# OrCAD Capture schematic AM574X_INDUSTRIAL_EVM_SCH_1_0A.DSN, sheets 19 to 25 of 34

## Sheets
19 Pg06: Power Supply 2: size C
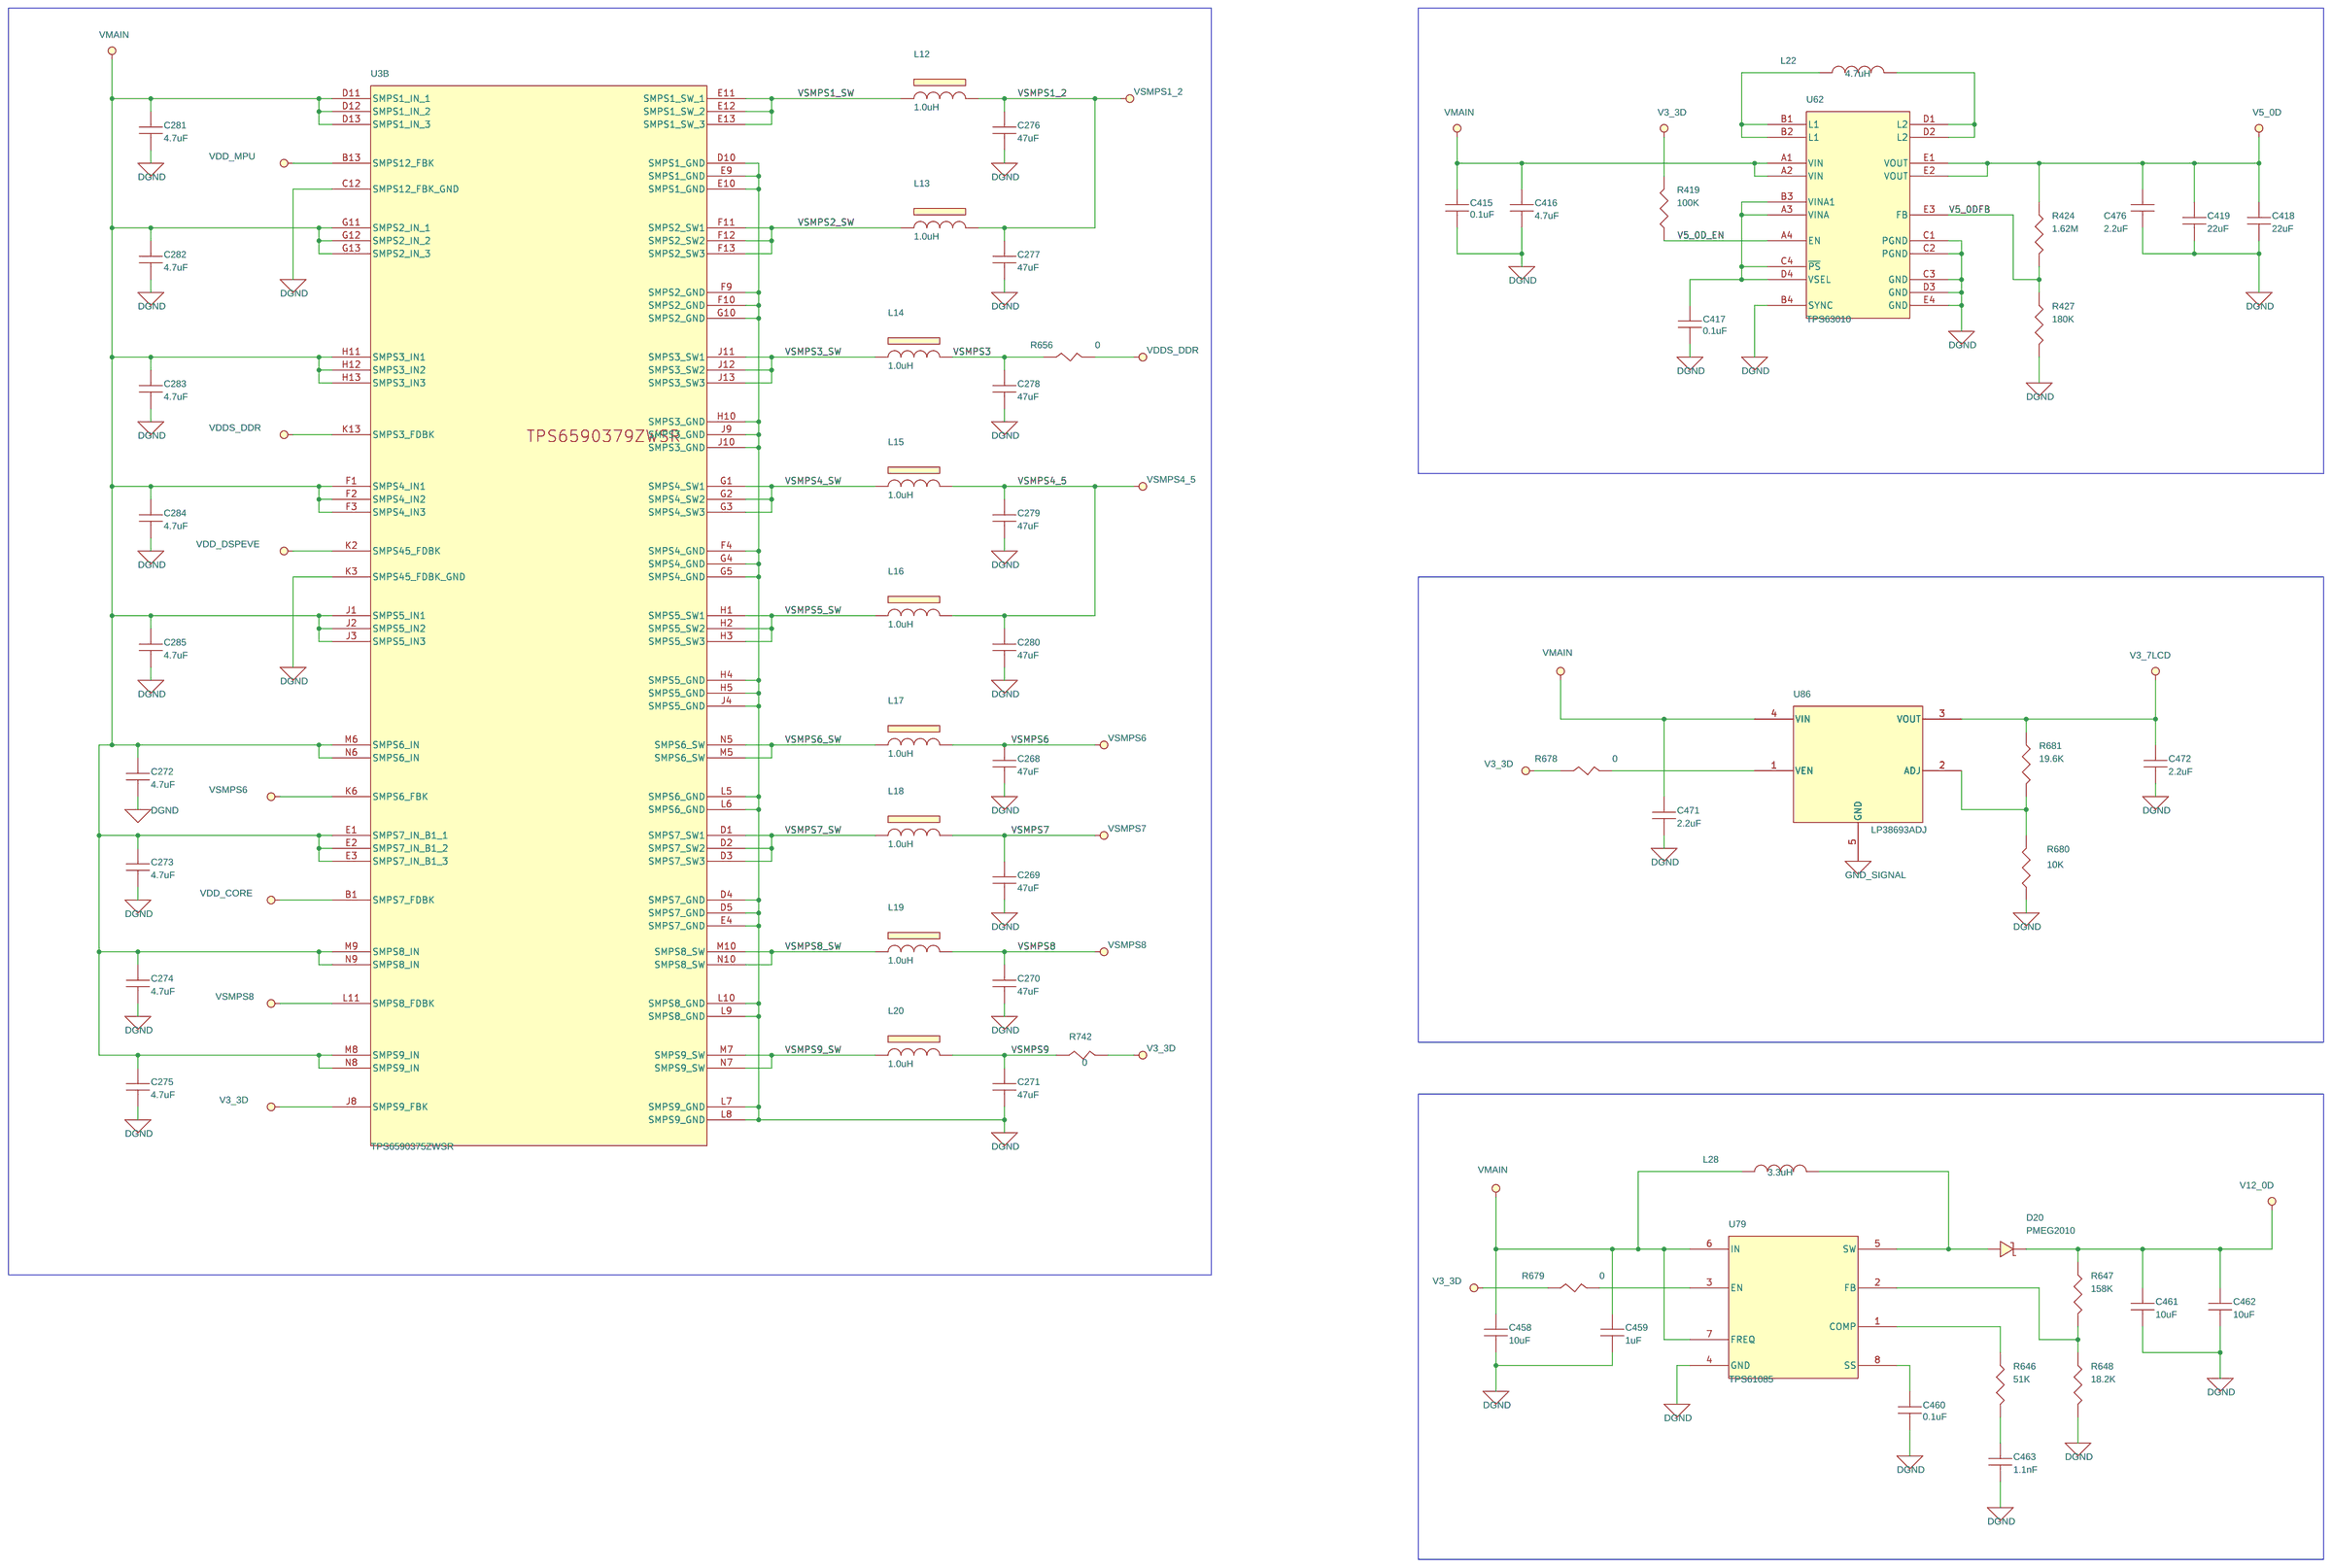
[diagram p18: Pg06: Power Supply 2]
20 Pg05: Power Supply 1: size C
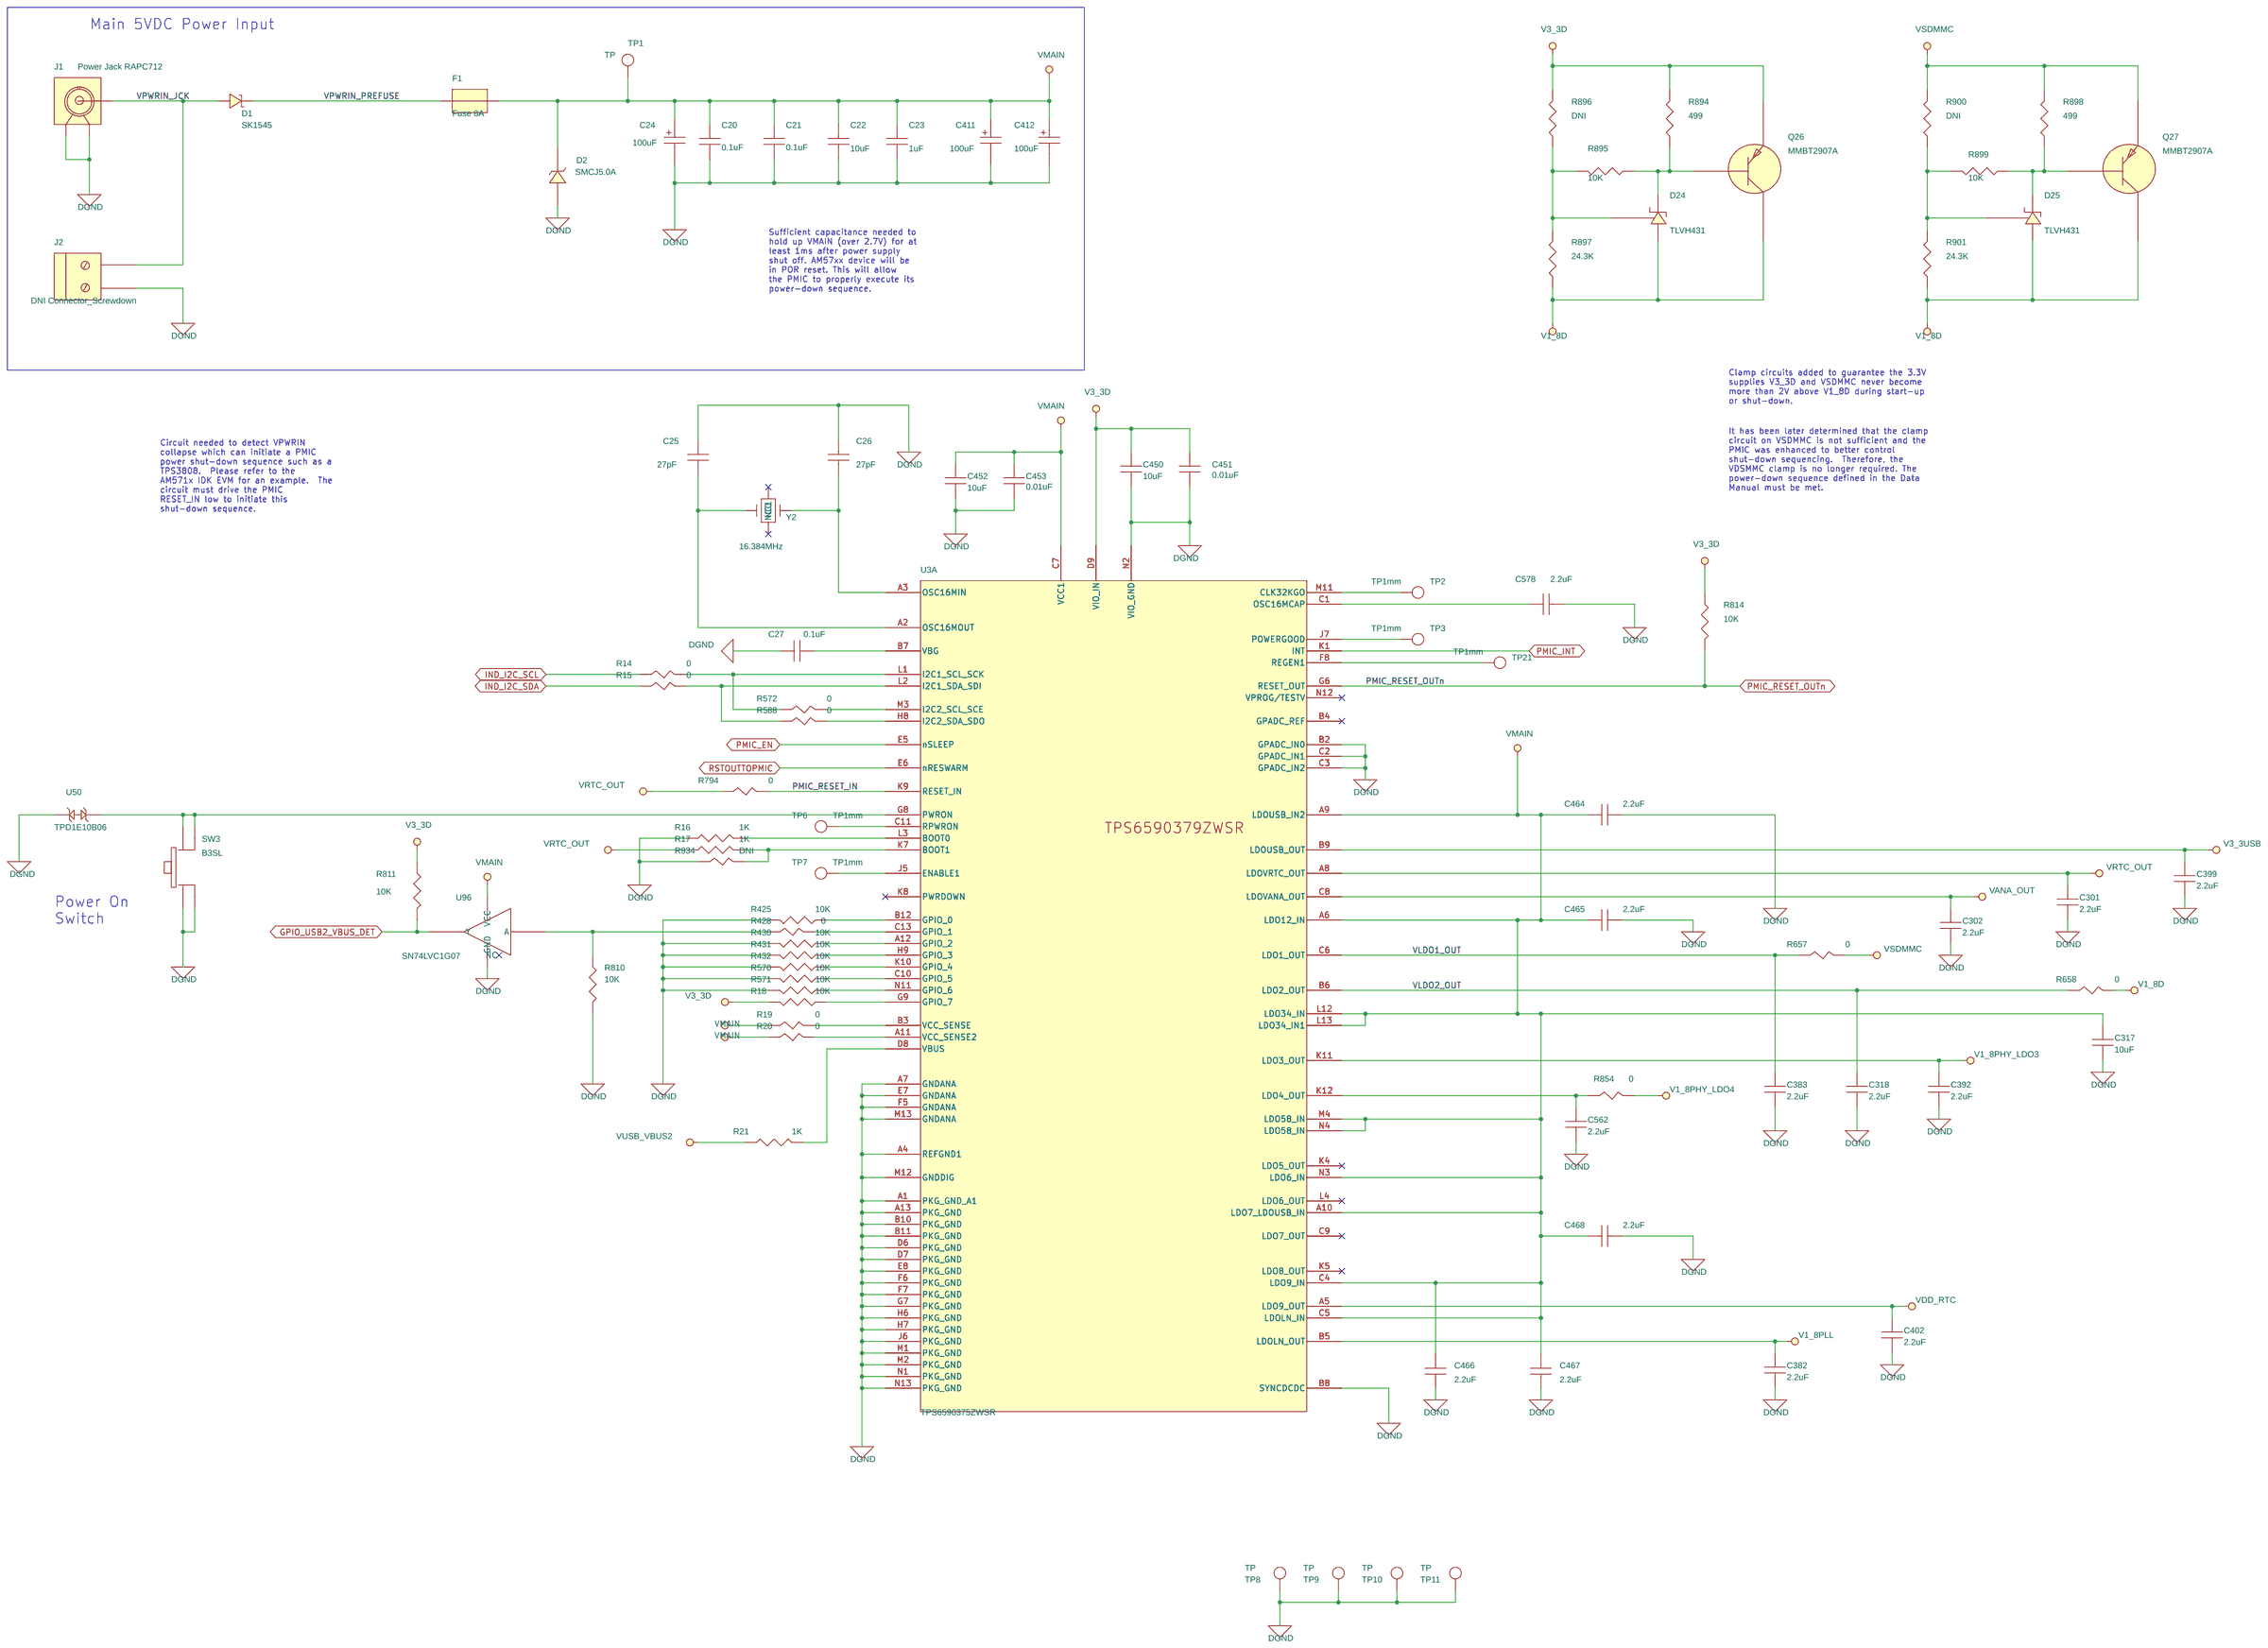
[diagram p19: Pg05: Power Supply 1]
21 Pg20: Industrial I/O: size C
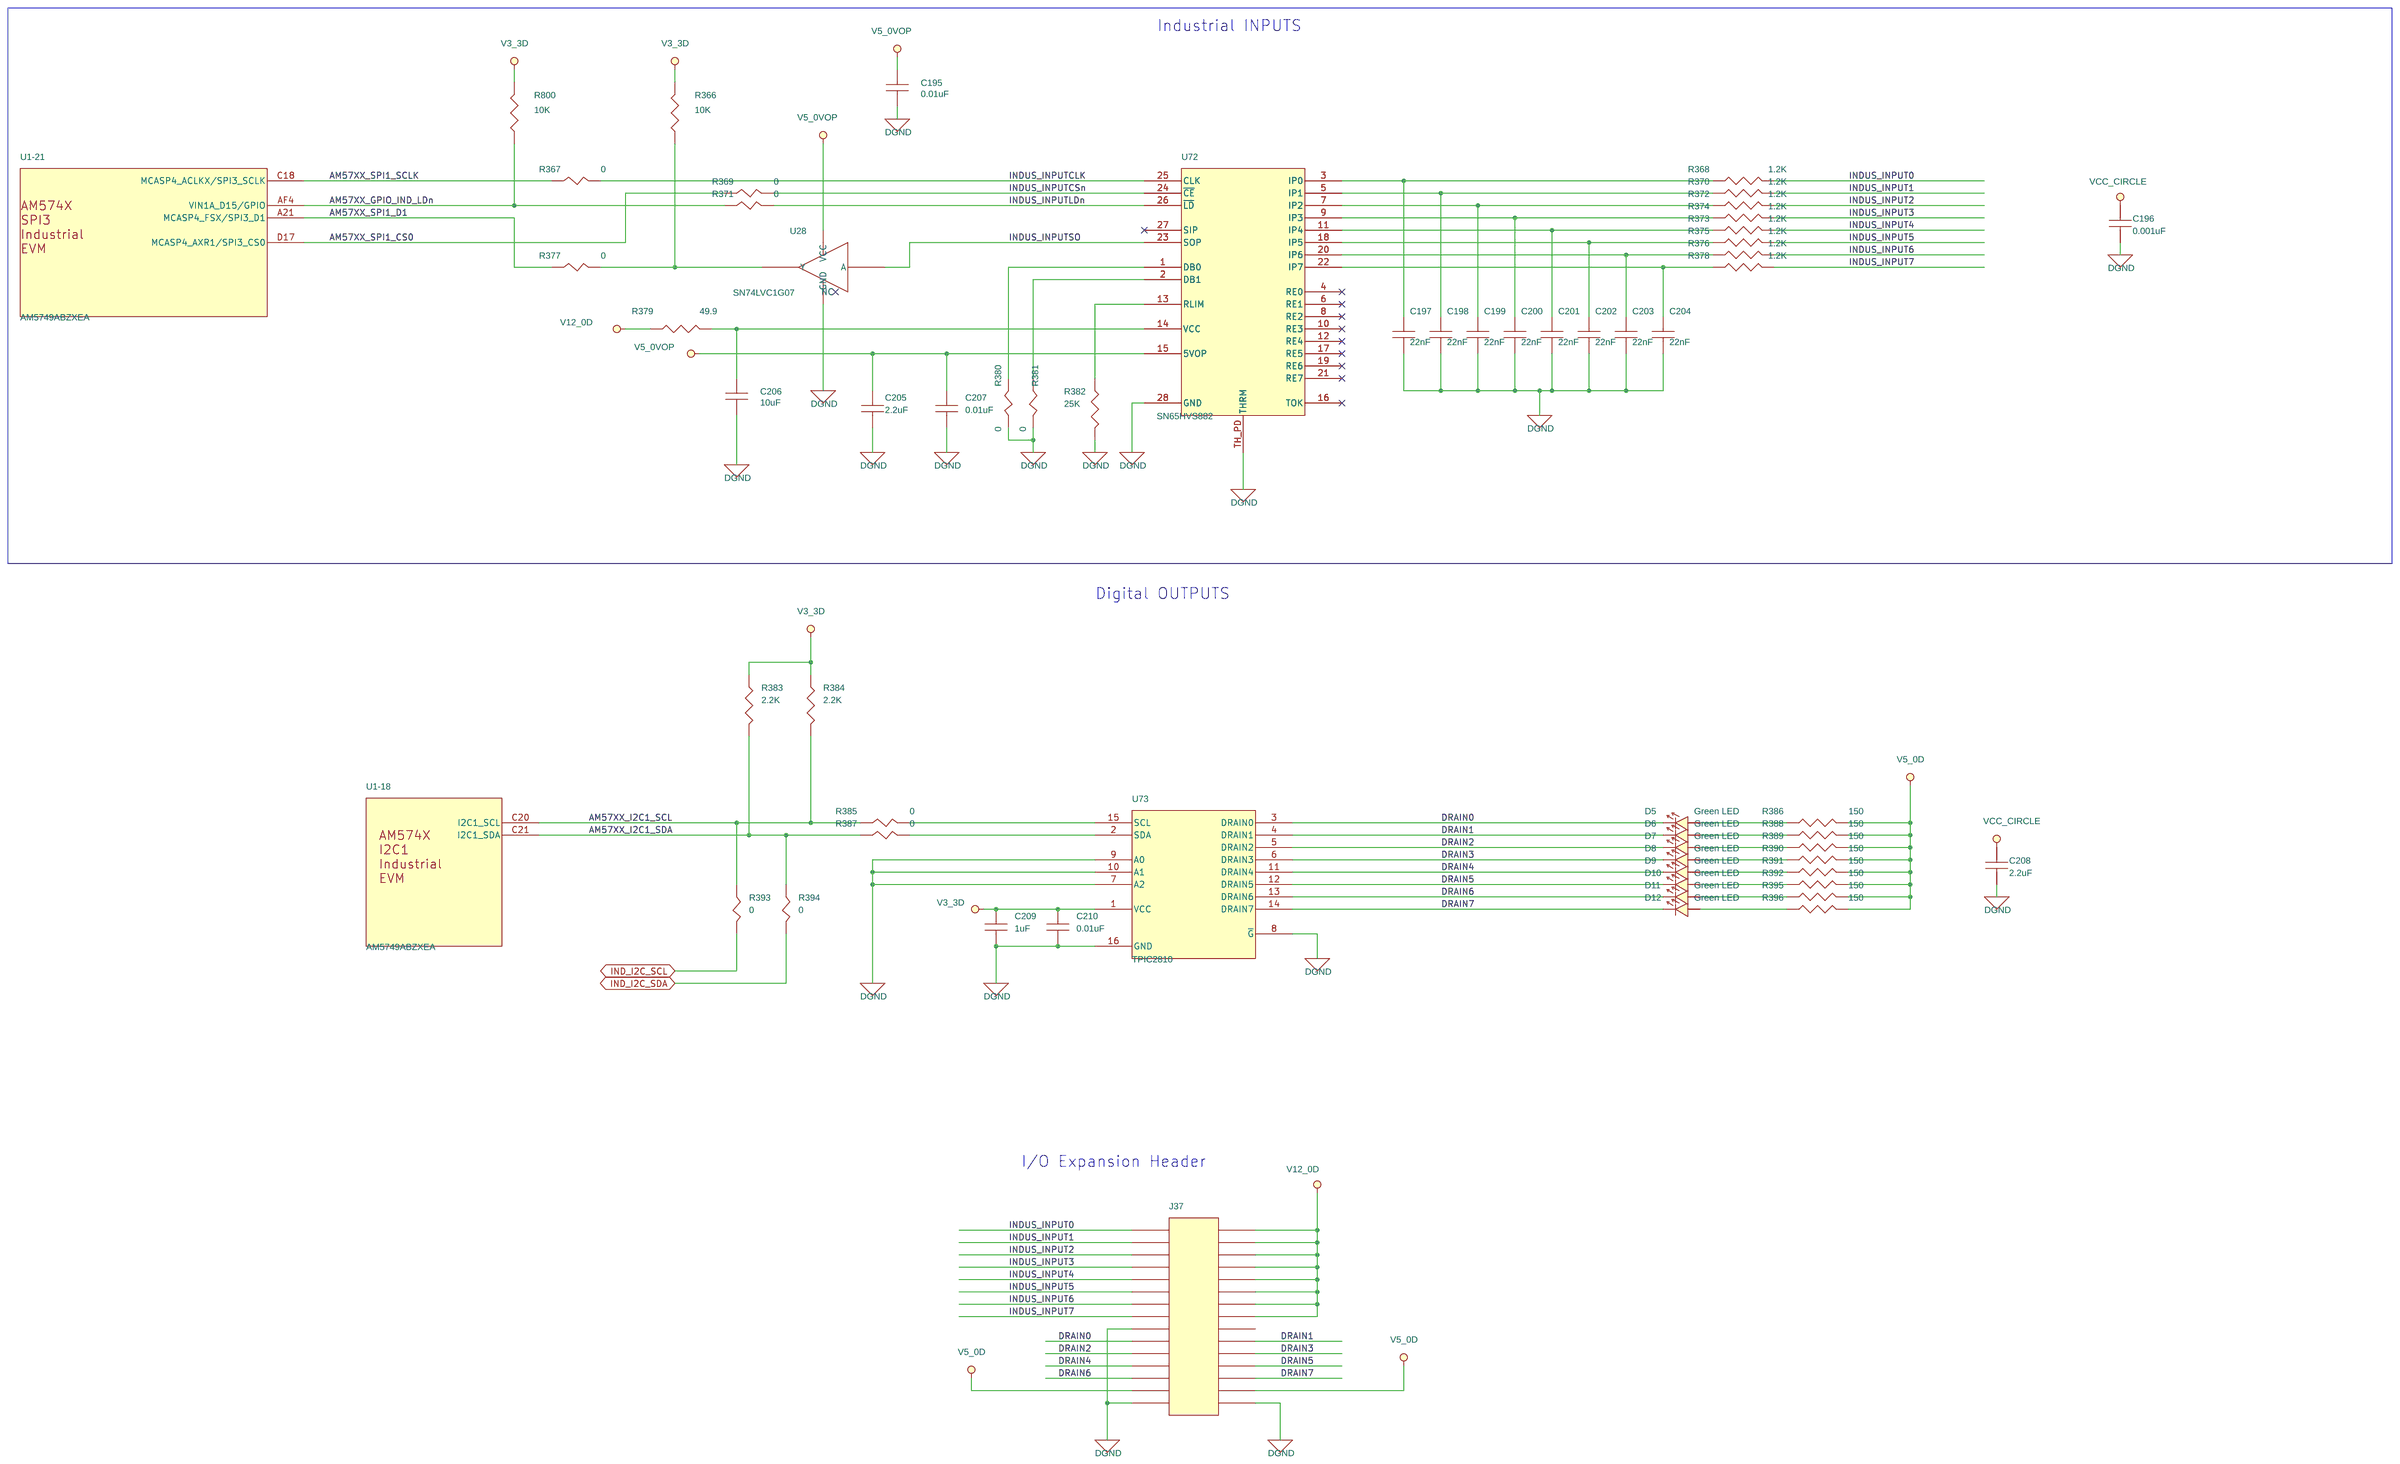
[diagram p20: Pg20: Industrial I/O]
22 Pg11: ICSS1 Ethernet 0: size C
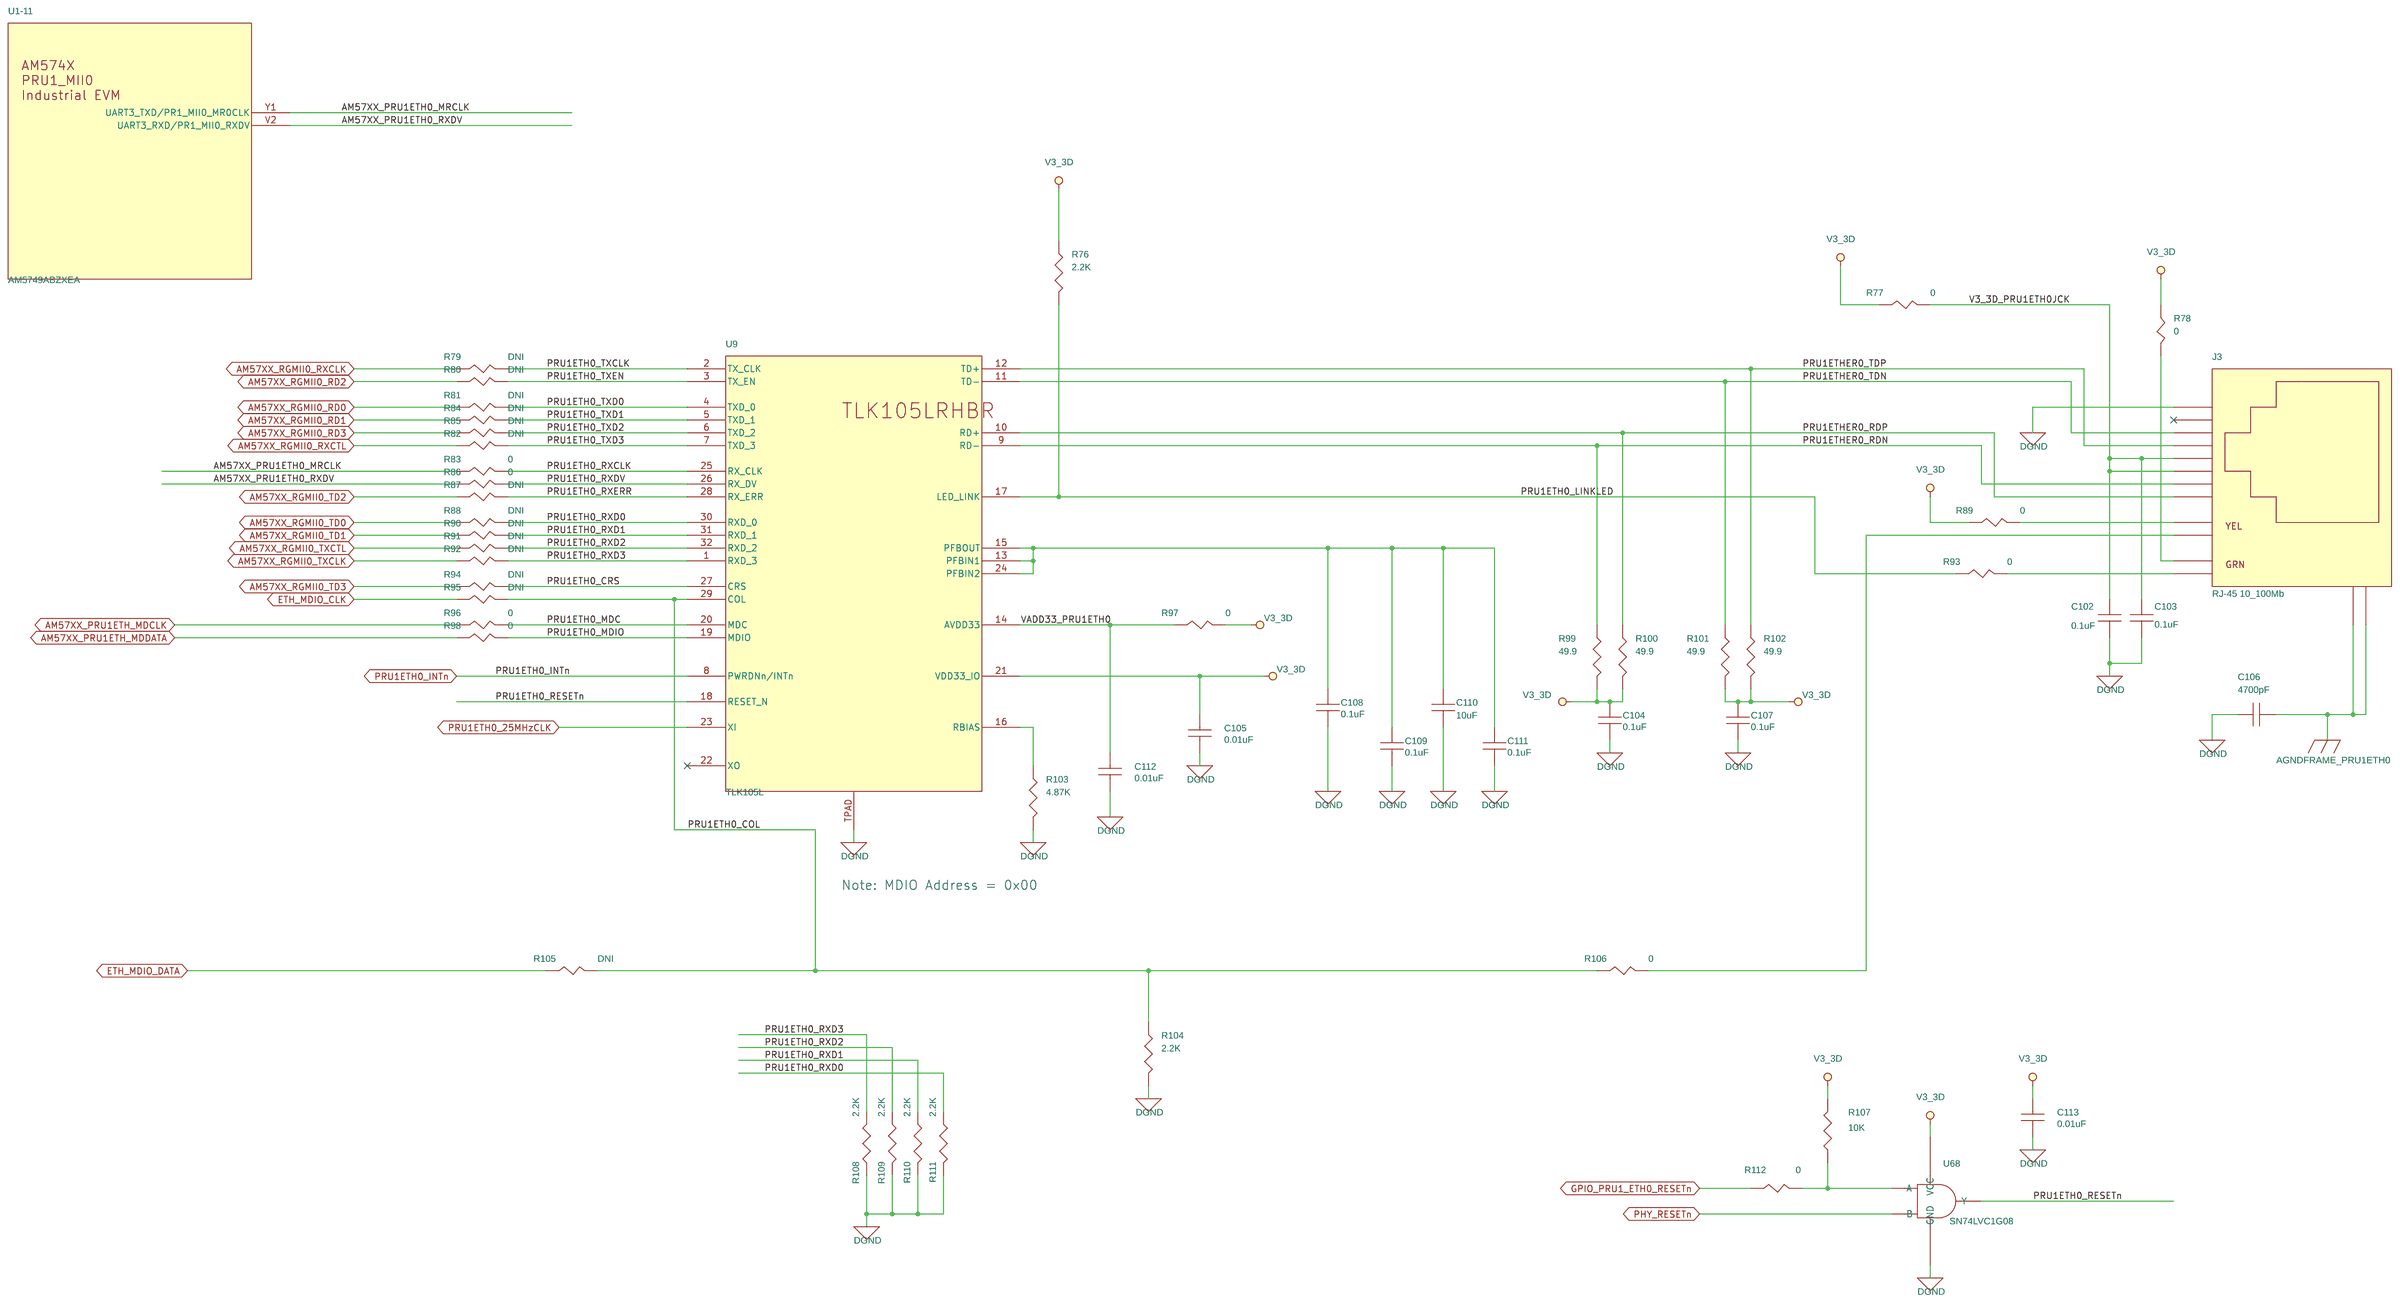
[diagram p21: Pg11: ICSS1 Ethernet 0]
23 Pg03: Processor Power: size C
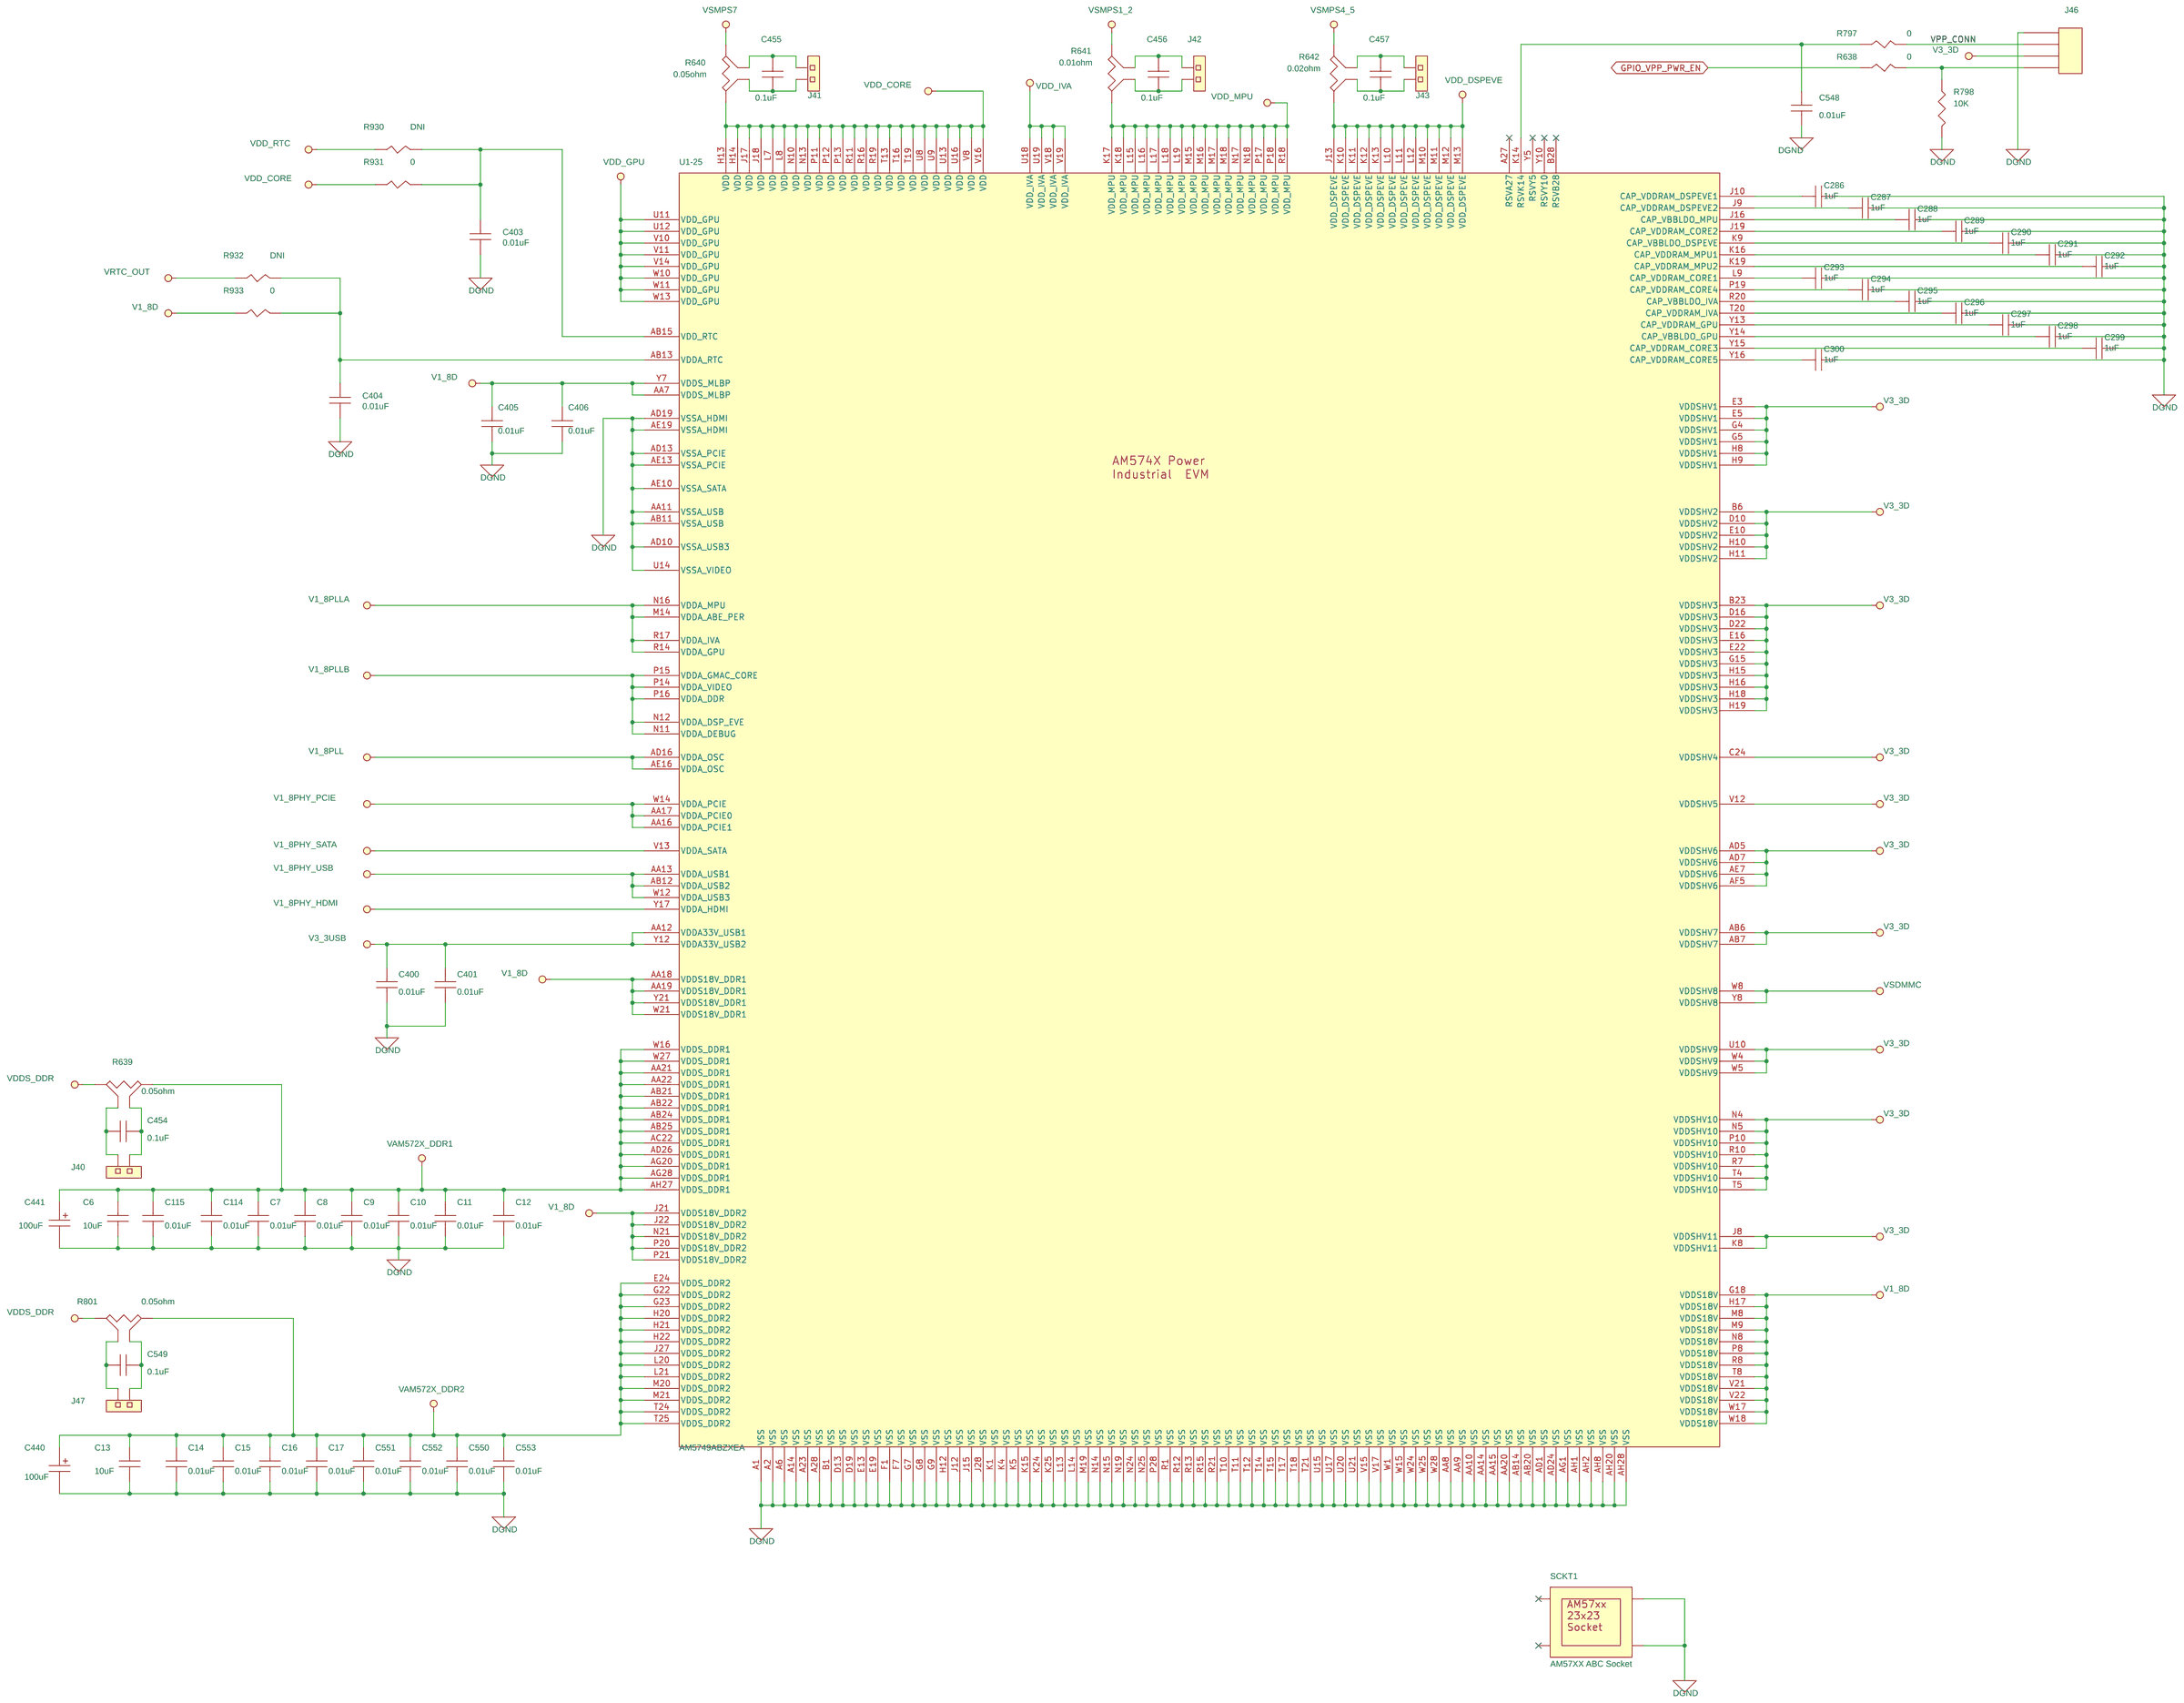
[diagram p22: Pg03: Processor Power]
24 Pg12: ICSS1 Ethernet 1: size C
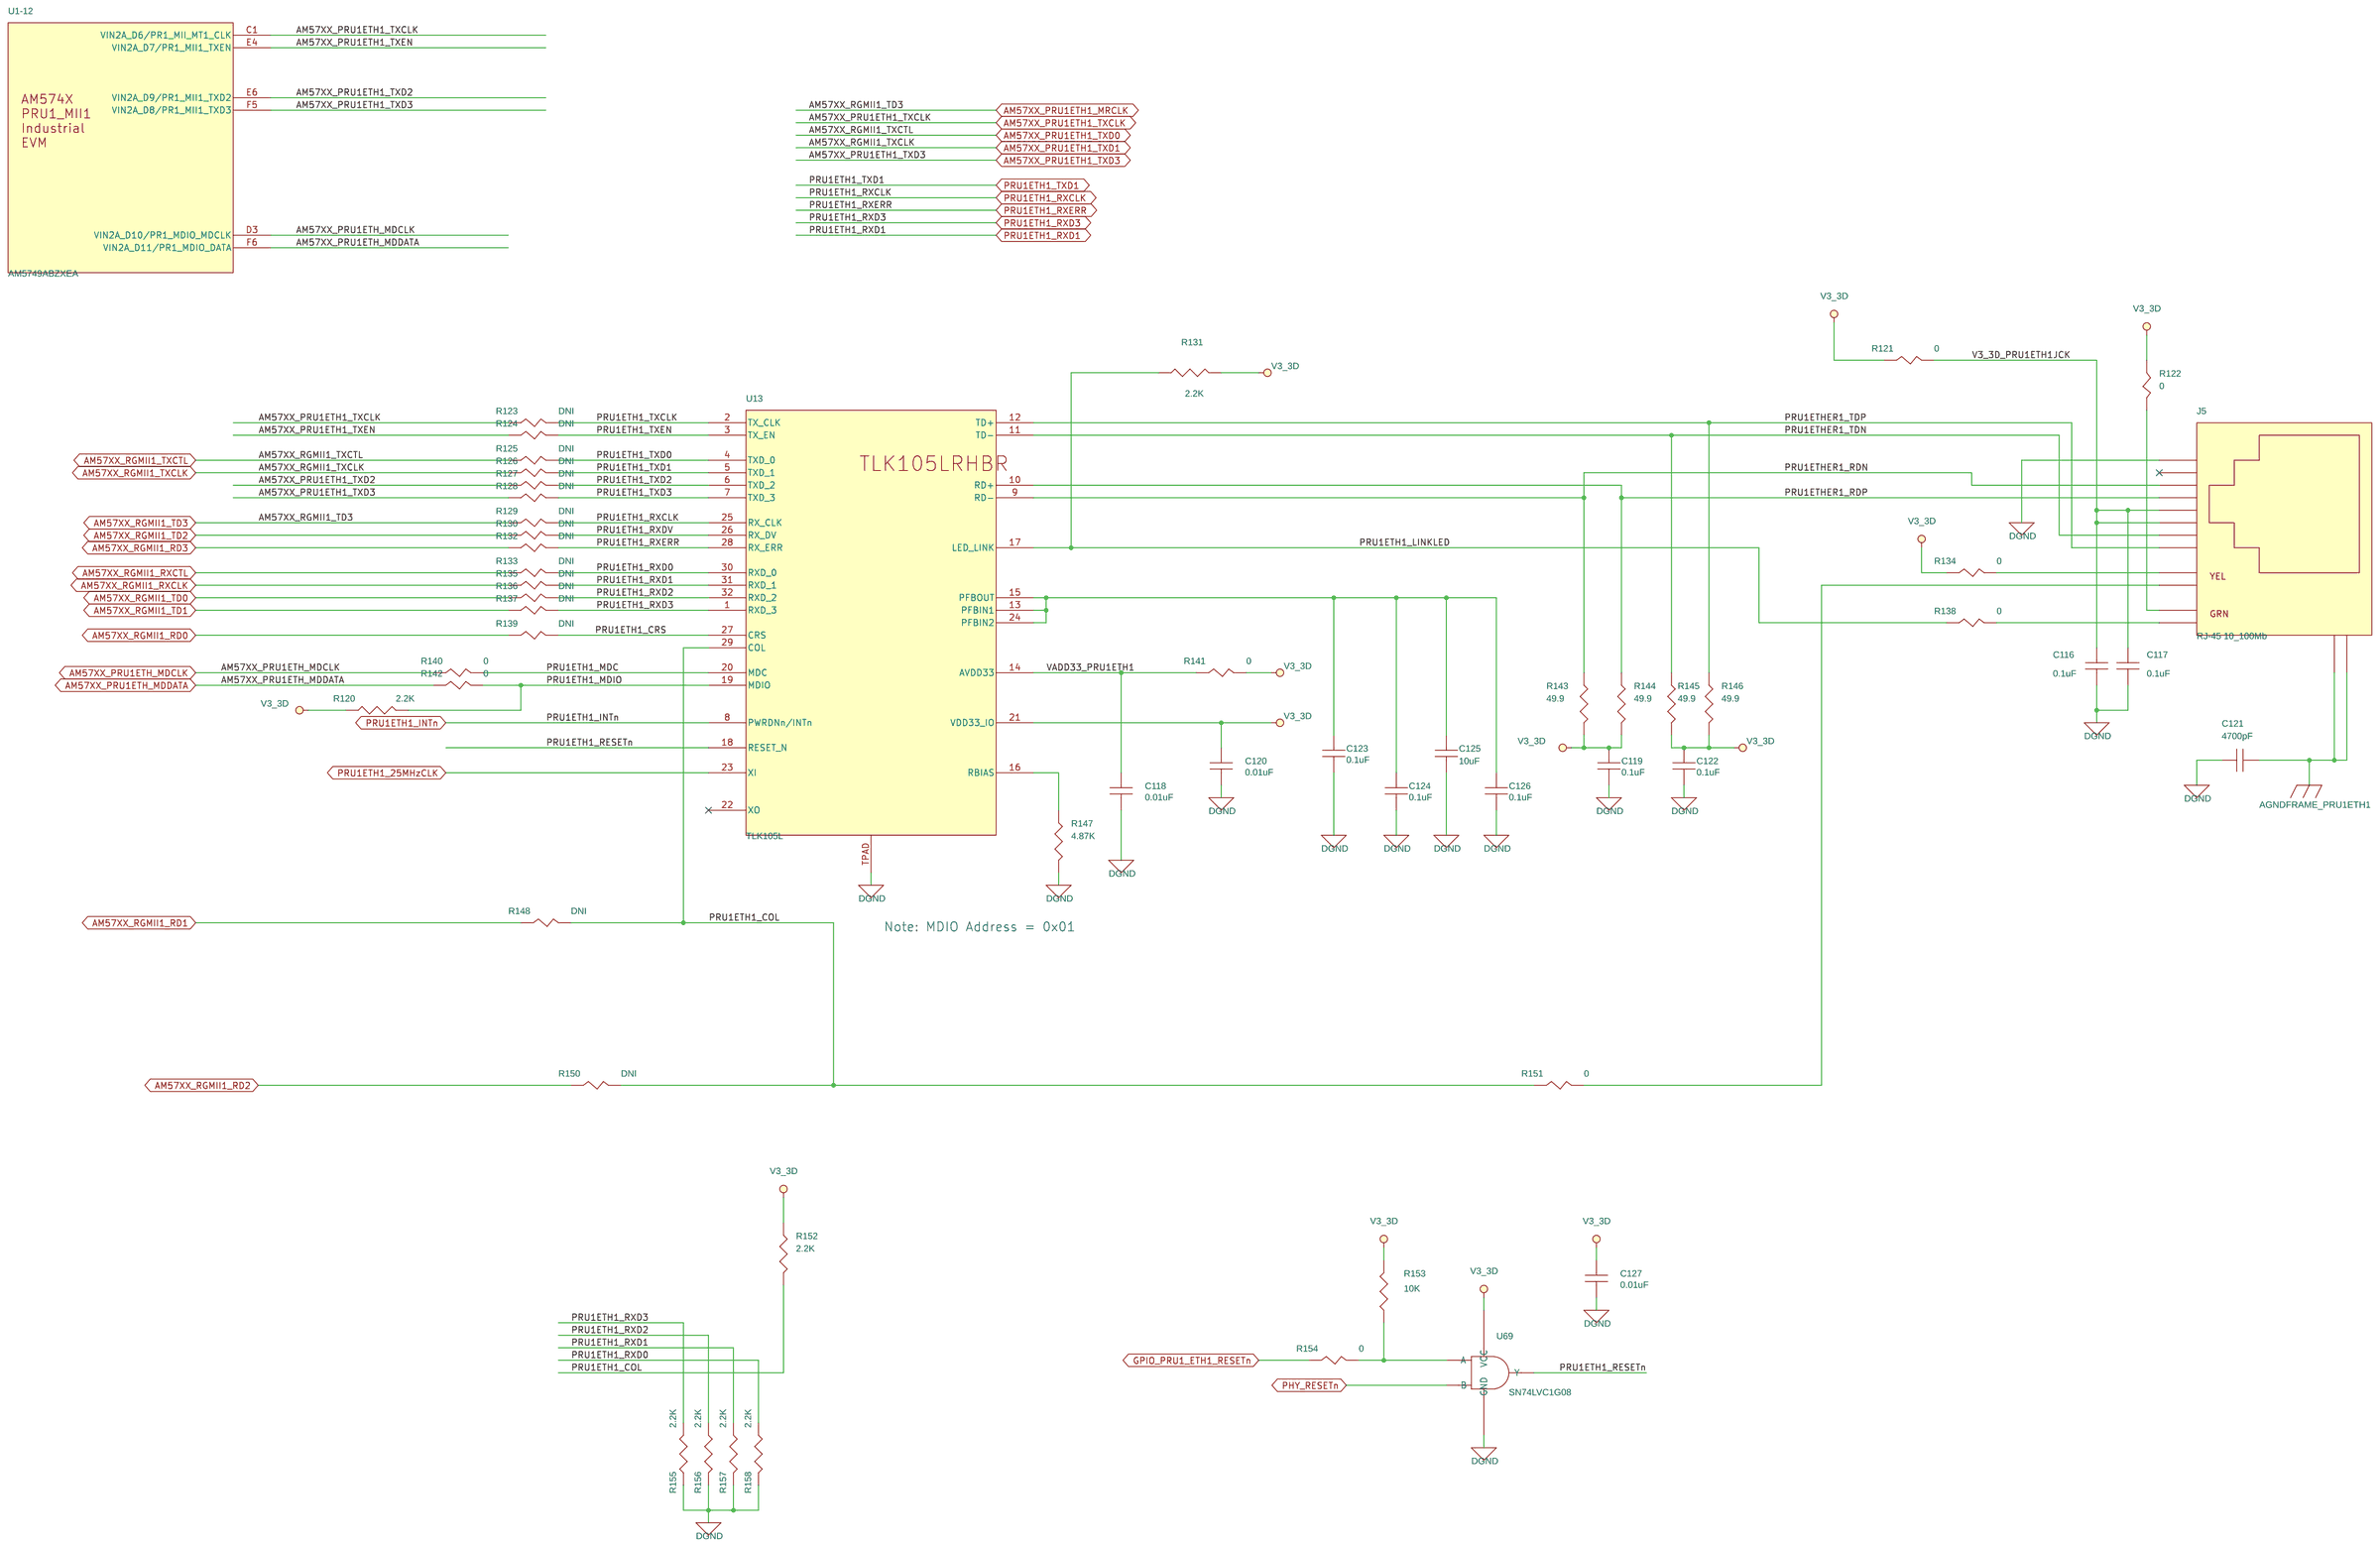
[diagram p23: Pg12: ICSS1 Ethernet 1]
25 Pg07: QSPI Flash Memory: size C
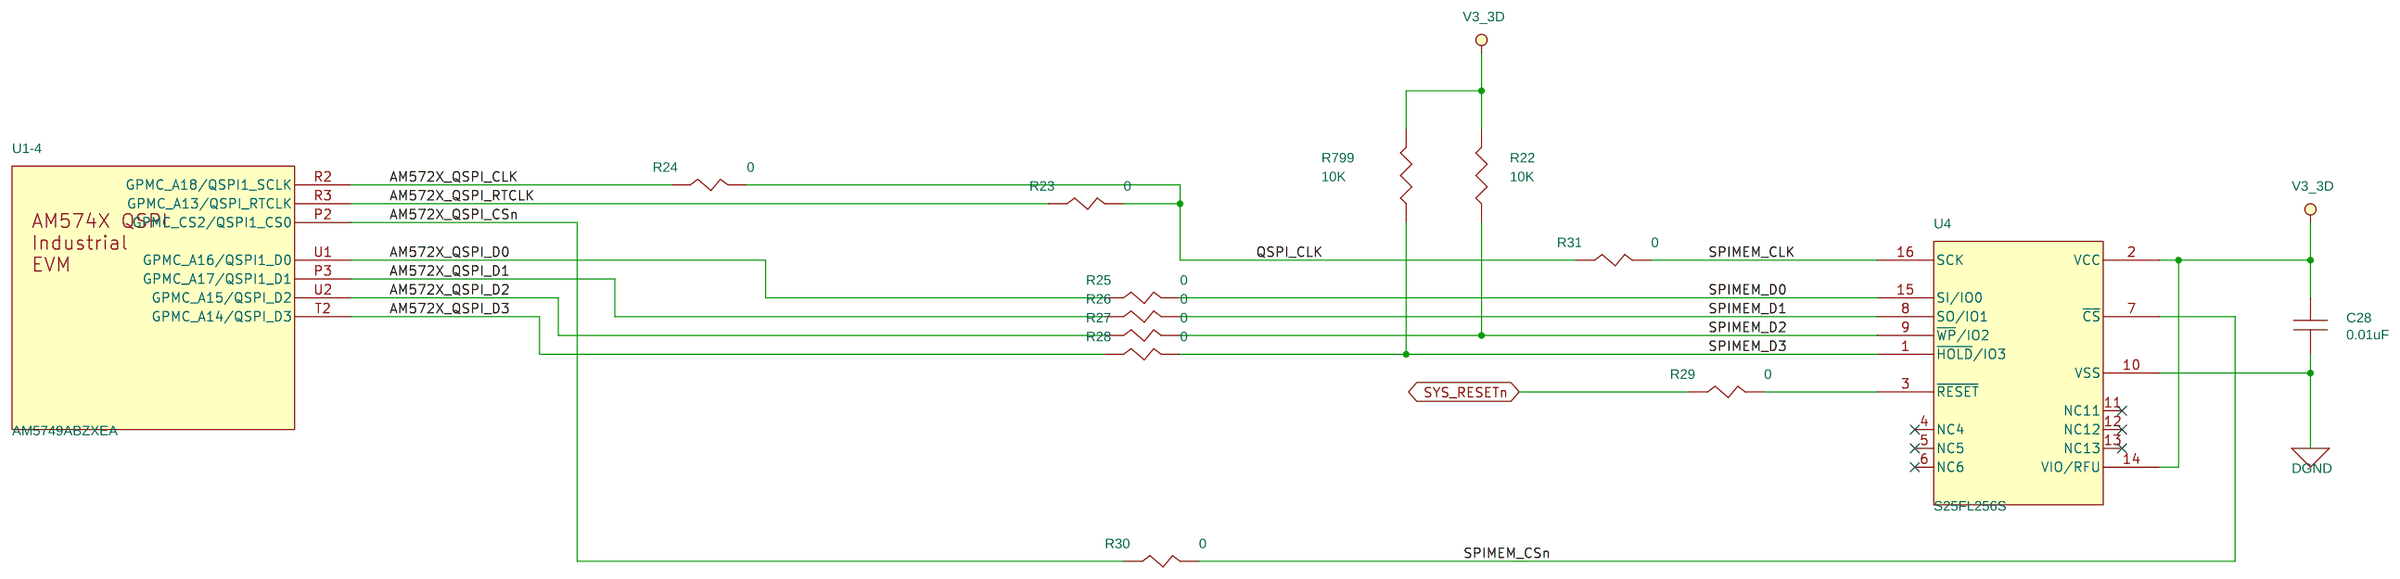
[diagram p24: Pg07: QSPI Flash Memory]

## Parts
sheet Pg03: Processor Power
C6  10uF  [SM-7351-CAP-0805]
C7  0.01uF  [SM-7351-CAP-0402]
C8  0.01uF  [SM-7351-CAP-0402]
C9  0.01uF  [SM-7351-CAP-0402]
C10  0.01uF  [SM-7351-CAP-0402]
C11  0.01uF  [SM-7351-CAP-0402]
C12  0.01uF  [SM-7351-CAP-0402]
C13  10uF  [SM-7351-CAP-0805]
C14  0.01uF  [SM-7351-CAP-0402]
C15  0.01uF  [SM-7351-CAP-0402]
C16  0.01uF  [SM-7351-CAP-0402]
C17  0.01uF  [SM-7351-CAP-0402]
C114  0.01uF  [SM-7351-CAP-0402]
C115  0.01uF  [SM-7351-CAP-0402]
C286  1uF  [SM-7351-CAP-0402]
C287  1uF  [SM-7351-CAP-0402]
C288  1uF  [SM-7351-CAP-0402]
C289  1uF  [SM-7351-CAP-0402]
C290  1uF  [SM-7351-CAP-0402]
C291  1uF  [SM-7351-CAP-0402]
C292  1uF  [SM-7351-CAP-0402]
C293  1uF  [SM-7351-CAP-0402]
C294  1uF  [SM-7351-CAP-0402]
C295  1uF  [SM-7351-CAP-0402]
C296  1uF  [SM-7351-CAP-0402]
C297  1uF  [SM-7351-CAP-0402]
C298  1uF  [SM-7351-CAP-0402]
C299  1uF  [SM-7351-CAP-0402]
C300  1uF  [SM-7351-CAP-0402]
C400  0.01uF  [SM-7351-CAP-0402]
C401  0.01uF  [SM-7351-CAP-0402]
C403  0.01uF  [SM-7351-CAP-0402]
C404  0.01uF  [SM-7351-CAP-0402]
C405  0.01uF  [SM-7351-CAP-0402]
C406  0.01uF  [SM-7351-CAP-0402]
C440  100uF  [SM-7351-CAP-smdcan]
C441  100uF  [SM-7351-CAP-smdcan]
C454  0.1uF  [SM-7351-CAP-0402]
C455  0.1uF  [SM-7351-CAP-0402]
C456  0.1uF  [SM-7351-CAP-0402]
C457  0.1uF  [SM-7351-CAP-0402]
C548  0.01uF  [SM-7351-CAP-0402]
C549  0.1uF  [SM-7351-CAP-0402]
C550  0.01uF  [SM-7351-CAP-0402]
C551  0.01uF  [SM-7351-CAP-0402]
C552  0.01uF  [SM-7351-CAP-0402]
C553  0.01uF  [SM-7351-CAP-0402]
J40  HEADER 2  [header_2x1]
J41  HEADER 2  [header_2x1]
J42  HEADER 2  [header_2x1]
J43  HEADER 2  [header_2x1]
J46  HEADER 4  [HDR1x4-330M]
J47  HEADER 2  [header_2x1]
R638  0  [SM-7351-RES-0402]
R639  0.05ohm  [SM_RES_LVK12]
R640  0.05ohm  [SM_RES_LVK12]
R641  0.01ohm  [SM_RES_LVK12]
R642  0.02ohm  [SM_RES_LVK12]
R797  0  [SM-7351-RES-0402]
R798  10K  [SM-7351-RES-0402]
R801  0.05ohm  [SM_RES_LVK12]
R930  DNI  [SM-7351-RES-0402]
R931  0  [SM-7351-RES-0402]
R932  DNI  [SM-7351-RES-0402]
R933  0  [SM-7351-RES-0402]
SCKT1  AM57XX ABC Socket  [SCK-SG-BGA-6334]
sheet Pg05: Power Supply 1
C20  0.1uF  [SM-7351-CAP-0402]
C21  0.1uF  [SM-7351-CAP-0402]
C22  10uF  [SM-7351-CAP-0805]
C23  1uF  [SM-7351-CAP-0603]
C24  100uF  [SM-7351-CAP-smdcan]
C25  27pF  [SM-7351-CAP-0402]
C26  27pF  [SM-7351-CAP-0402]
C27  0.1uF  [SM-7351-CAP-0402]
C301  2.2uF  [SM-7351-CAP-0402]
C302  2.2uF  [SM-7351-CAP-0402]
C317  10uF  [SM-7351-CAP-0805]
C318  2.2uF  [SM-7351-CAP-0402]
C382  2.2uF  [SM-7351-CAP-0402]
C383  2.2uF  [SM-7351-CAP-0402]
C392  2.2uF  [SM-7351-CAP-0402]
C399  2.2uF  [SM-7351-CAP-0402]
C402  2.2uF  [SM-7351-CAP-0402]
C411  100uF  [SM-7351-CAP-smdcan]
C412  100uF  [SM-7351-CAP-smdcan]
C450  10uF  [SM-7351-CAP-0603]
C451  0.01uF  [SM-7351-CAP-0402]
C452  10uF  [SM-7351-CAP-0603]
C453  0.01uF  [SM-7351-CAP-0402]
C464  2.2uF  [SM-7351-CAP-0805]
C465  2.2uF  [SM-7351-CAP-0805]
C466  2.2uF  [SM-7351-CAP-0805]
C467  2.2uF  [SM-7351-CAP-0805]
C468  2.2uF  [SM-7351-CAP-0805]
C562  2.2uF  [SM-7351-CAP-0402]
C578  2.2uF  [SM-7351-CAP-0805]
D1  SK1545  [sk1545]
D2  SMCJ5.0A  [SMCJ26CA]
D24  TLVH431  [sot23-3-44m]
D25  TLVH431  [sot23-3-44m]
F1  Fuse 8A  [fuse-0154]
J1  Power Jack RAPC712  [RAPC712]
J2  DNI Connector_Screwdown  [conn_osttc02]
Q26  MMBT2907A  [sot23-3-44m]
Q27  MMBT2907A  [sot23-3-44m]
R14  0  [SM-7351-RES-0402]
R15  0  [SM-7351-RES-0402]
R16  1K  [SM-7351-RES-0402]
R17  1K  [SM-7351-RES-0402]
R18  10K  [SM-7351-RES-0402]
R19  0  [SM-7351-RES-0402]
R20  0  [SM-7351-RES-0402]
R21  1K  [SM-7351-RES-0402]
R425  10K  [SM-7351-RES-0402]
R428  0  [SM-7351-RES-0402]
R430  10K  [SM-7351-RES-0402]
R431  10K  [SM-7351-RES-0402]
R432  10K  [SM-7351-RES-0402]
R570  10K  [SM-7351-RES-0402]
R571  10K  [SM-7351-RES-0402]
R572  0  [SM-7351-RES-0402]
R588  0  [SM-7351-RES-0402]
R657  0  [SM-7351-RES-0402]
R658  0  [SM-7351-RES-0402]
R794  0  [SM-7351-RES-0402]
R810  10K  [SM-7351-RES-0402]
R811  10K  [SM-7351-RES-0402]
R814  10K  [SM-7351-RES-0402]
R854  0  [SM-7351-RES-0402]
R894  499  [SM-7351-RES-0402]
R895  10K  [SM-7351-RES-0402]
R896  DNI  [SM-7351-RES-0402]
R897  24.3K  [SM-7351-RES-0402]
R898  499  [SM-7351-RES-0402]
R899  10K  [SM-7351-RES-0402]
R900  DNI  [SM-7351-RES-0402]
R901  24.3K  [SM-7351-RES-0402]
R934  DNI  [SM-7351-RES-0402]
SW3  B3SL  [SW_B3SL-1022P]
TP1  TP  [TH_TP_5002]
TP2  TP1mm  [tp_smd1mmcircle]
TP3  TP1mm  [tp_smd1mmcircle]
TP6  TP1mm  [tp_smd1mmcircle]
TP7  TP1mm  [tp_smd1mmcircle]
TP8  TP  [TH_TP_5002]
TP9  TP  [TH_TP_5002]
TP10  TP  [TH_TP_5002]
TP11  TP  [TH_TP_5002]
TP21  TP1mm  [tp_smd1mmcircle]
U50  TPD1E10B06  [tpd1e10b06-2l]
U96  SN74LVC1G07  [SC70-5-43M]
Y2  16.384MHz  [xtal3225-39m]
sheet Pg06: Power Supply 2
C268  47uF  [SM-7351-CAP-1206]
C269  47uF  [SM-7351-CAP-1206]
C270  47uF  [SM-7351-CAP-1206]
C271  47uF  [SM-7351-CAP-1206]
C272  4.7uF  [SM-7351-CAP-0603]
C273  4.7uF  [SM-7351-CAP-0603]
C274  4.7uF  [SM-7351-CAP-0603]
C275  4.7uF  [SM-7351-CAP-0603]
C276  47uF  [SM-7351-CAP-1206]
C277  47uF  [SM-7351-CAP-1206]
C278  47uF  [SM-7351-CAP-1206]
C279  47uF  [SM-7351-CAP-1206]
C280  47uF  [SM-7351-CAP-1206]
C281  4.7uF  [SM-7351-CAP-0603]
C282  4.7uF  [SM-7351-CAP-0603]
C283  4.7uF  [SM-7351-CAP-0603]
C284  4.7uF  [SM-7351-CAP-0603]
C285  4.7uF  [SM-7351-CAP-0603]
C415  0.1uF  [SM-7351-CAP-0402]
C416  4.7uF  [SM-7351-CAP-0603]
C417  0.1uF  [SM-7351-CAP-0402]
C418  22uF  [SM-7351-CAP-0805]
C419  22uF  [SM-7351-CAP-0805]
C458  10uF  [SM-7351-CAP-0805]
C459  1uF  [SM-7351-CAP-0603]
C460  0.1uF  [SM-7351-CAP-0402]
C461  10uF  [SM-7351-CAP-0805]
C462  10uF  [SM-7351-CAP-0805]
C463  1.1nF  [SM-7351-CAP-0603]
C471  2.2uF  [SM-7351-CAP-0805]
C472  2.2uF  [SM-7351-CAP-0805]
C476  2.2uF  [SM-7351-CAP-0402]
D20  PMEG2010  [DFN1006D-2]
L12  1.0uH  [ind_ihlp1616ab]
L13  1.0uH  [ind_ihlp1616ab]
L14  1.0uH  [ind_ihlp1616ab]
L15  1.0uH  [ind_ihlp1616ab]
L16  1.0uH  [ind_ihlp1616ab]
L17  1.0uH  [ind_ihlp1616ab]
L18  1.0uH  [ind_ihlp1616ab]
L19  1.0uH  [ind_ihlp1616ab]
L20  1.0uH  [ind_ihlp1616ab]
L22  4.7uH  [smd_slf7055t]
L28  3.3uH  [vlcf5020t]
R419  100K  [SM-7351-RES-0402]
R424  1.62M  [SM-7351-RES-0402]
R427  180K  [SM-7351-RES-0402]
R646  51K  [SM-7351-RES-0402]
R647  158K  [SM-7351-RES-0402]
R648  18.2K  [SM-7351-RES-0402]
R656  0  [SM-7351-RES-0603]
R678  0  [SM-7351-RES-0402]
R679  0  [SM-7351-RES-0402]
R680  10K  [SM-7351-RES-0402]
R681  19.6K  [SM-7351-RES-0402]
R742  0  [SM-7351-RES-0603]
U3  TPS6590375ZWSR  [bga12x12-169-55m]  (sections A,B)
U62  TPS63010  [u_20_dsbga]
U79  TPS61085  [MSOP3X3-8-43M]
U86  LP38693ADJ  [SOT-223-5]
sheet Pg07: QSPI Flash Memory
C28  0.01uF  [SM-7351-CAP-0402]
R22  10K  [SM-7351-RES-0402]
R23  0  [SM-7351-RES-0402]
R24  0  [SM-7351-RES-0402]
R25  0  [SM-7351-RES-0402]
R26  0  [SM-7351-RES-0402]
R27  0  [SM-7351-RES-0402]
R28  0  [SM-7351-RES-0402]
R29  0  [SM-7351-RES-0402]
R30  0  [SM-7351-RES-0402]
R31  0  [SM-7351-RES-0402]
R799  10K  [SM-7351-RES-0402]
U4  S25FL256S  [soic_16pin_dw]
sheet Pg11: ICSS1 Ethernet 0
C102  0.1uF  [SM-7351-CAP-0402]
C103  0.1uF  [SM-7351-CAP-0402]
C104  0.1uF  [SM-7351-CAP-0402]
C105  0.01uF  [SM-7351-CAP-0402]
C106  4700pF  [SM-7351-CAP-0402]
C107  0.1uF  [SM-7351-CAP-0402]
C108  0.1uF  [SM-7351-CAP-0402]
C109  0.1uF  [SM-7351-CAP-0402]
C110  10uF  [SM-7351-CAP-0805]
C111  0.1uF  [SM-7351-CAP-0402]
C112  0.01uF  [SM-7351-CAP-0402]
C113  0.01uF  [SM-7351-CAP-0402]
J3  RJ-45 10_100Mb  [CNRJ45-1X1WLED]
R76  2.2K  [sm-7351-res-0402]
R77  0  [SM-7351-RES-0402]
R78  0  [SM-7351-RES-0402]
R79  DNI  [SM-7351-RES-0402]
R80  DNI  [SM-7351-RES-0402]
R81  DNI  [SM-7351-RES-0402]
R82  DNI  [SM-7351-RES-0402]
R83  0  [SM-7351-RES-0402]
R84  DNI  [SM-7351-RES-0402]
R85  DNI  [SM-7351-RES-0402]
R86  0  [SM-7351-RES-0402]
R87  DNI  [SM-7351-RES-0402]
R88  DNI  [SM-7351-RES-0402]
R89  0  [SM-7351-RES-0402]
R90  DNI  [SM-7351-RES-0402]
R91  DNI  [SM-7351-RES-0402]
R92  DNI  [SM-7351-RES-0402]
R93  0  [SM-7351-RES-0402]
R94  DNI  [SM-7351-RES-0402]
R95  DNI  [SM-7351-RES-0402]
R96  0  [SM-7351-RES-0402]
R97  0  [SM-7351-RES-0603]
R98  0  [SM-7351-RES-0402]
R99  49.9  [SM-7351-RES-0402]
R100  49.9  [SM-7351-RES-0402]
R101  49.9  [SM-7351-RES-0402]
R102  49.9  [SM-7351-RES-0402]
R103  4.87K  [SM-7351-RES-0402]
R104  2.2K  [sm-7351-res-0402]
R105  DNI  [SM-7351-RES-0402]
R106  0  [SM-7351-RES-0402]
R107  10K  [SM-7351-RES-0402]
R108  2.2K  [sm-7351-res-0402]
R109  2.2K  [sm-7351-res-0402]
R110  2.2K  [sm-7351-res-0402]
R111  2.2K  [sm-7351-res-0402]
R112  0  [SM-7351-RES-0402]
U9  TLK105L  [qfn5x5-32-39m]
U68  SN74LVC1G08  [sm-so-sc70-5]
sheet Pg12: ICSS1 Ethernet 1
C116  0.1uF  [SM-7351-CAP-0402]
C117  0.1uF  [SM-7351-CAP-0402]
C118  0.01uF  [SM-7351-CAP-0402]
C119  0.1uF  [SM-7351-CAP-0402]
C120  0.01uF  [SM-7351-CAP-0402]
C121  4700pF  [SM-7351-CAP-0402]
C122  0.1uF  [SM-7351-CAP-0402]
C123  0.1uF  [SM-7351-CAP-0402]
C124  0.1uF  [SM-7351-CAP-0402]
C125  10uF  [SM-7351-CAP-0805]
C126  0.1uF  [SM-7351-CAP-0402]
C127  0.01uF  [SM-7351-CAP-0402]
J5  RJ-45 10_100Mb  [CNRJ45-1X1WLED]
R120  2.2K  [sm-7351-res-0402]
R121  0  [SM-7351-RES-0402]
R122  0  [SM-7351-RES-0402]
R123  DNI  [SM-7351-RES-0402]
R124  DNI  [SM-7351-RES-0402]
R125  DNI  [SM-7351-RES-0402]
R126  DNI  [SM-7351-RES-0402]
R127  DNI  [SM-7351-RES-0402]
R128  DNI  [SM-7351-RES-0402]
R129  DNI  [SM-7351-RES-0402]
R130  DNI  [SM-7351-RES-0402]
R131  2.2K  [sm-7351-res-0402]
R132  DNI  [SM-7351-RES-0402]
R133  DNI  [SM-7351-RES-0402]
R134  0  [SM-7351-RES-0402]
R135  DNI  [SM-7351-RES-0402]
R136  DNI  [SM-7351-RES-0402]
R137  DNI  [SM-7351-RES-0402]
R138  0  [SM-7351-RES-0603]
R139  DNI  [SM-7351-RES-0402]
R140  0  [SM-7351-RES-0402]
R141  0  [SM-7351-RES-0603]
R142  0  [SM-7351-RES-0402]
R143  49.9  [SM-7351-RES-0402]
R144  49.9  [SM-7351-RES-0402]
R145  49.9  [SM-7351-RES-0402]
R146  49.9  [SM-7351-RES-0402]
R147  4.87K  [SM-7351-RES-0402]
R148  DNI  [SM-7351-RES-0402]
R150  DNI  [SM-7351-RES-0402]
R151  0  [SM-7351-RES-0402]
R152  2.2K  [sm-7351-res-0402]
R153  10K  [SM-7351-RES-0402]
R154  0  [SM-7351-RES-0402]
R155  2.2K  [sm-7351-res-0402]
R156  2.2K  [sm-7351-res-0402]
R157  2.2K  [sm-7351-res-0402]
R158  2.2K  [sm-7351-res-0402]
U13  TLK105L  [qfn5x5-32-39m]
U69  SN74LVC1G08  [sm-so-sc70-5]
sheet Pg20: Industrial I/O
C195  0.01uF  [SM-7351-CAP-0402]
C196  0.001uF  [SM-7351-CAP-0402]
C197  22nF  [SM-7351-CAP-0402]
C198  22nF  [SM-7351-CAP-0402]
C199  22nF  [SM-7351-CAP-0402]
C200  22nF  [SM-7351-CAP-0402]
C201  22nF  [SM-7351-CAP-0402]
C202  22nF  [SM-7351-CAP-0402]
C203  22nF  [SM-7351-CAP-0402]
C204  22nF  [SM-7351-CAP-0402]
C205  2.2uF  [SM-7351-CAP-0805]
C206  10uF  [SM-7351-CAP-1206]
C207  0.01uF  [SM-7351-CAP-0402]
C208  2.2uF  [SM-7351-CAP-0805]
C209  1uF  [SM-7351-CAP-0402]
C210  0.01uF  [SM-7351-CAP-0402]
D5  Green LED  [sm_led_0805]
D6  Green LED  [sm_led_0805]
D7  Green LED  [sm_led_0805]
D8  Green LED  [sm_led_0805]
D9  Green LED  [sm_led_0805]
D10  Green LED  [sm_led_0805]
D11  Green LED  [sm_led_0805]
D12  Green LED  [sm_led_0805]
J37  Header 15x2 Female  [HDR2X15-344M]
R366  10K  [SM-7351-RES-0402]
R367  0  [SM-7351-RES-0402]
R368  1.2K  [SM-7351-CAP-0805]
R369  0  [SM-7351-RES-0402]
R370  1.2K  [SM-7351-CAP-0805]
R371  0  [SM-7351-RES-0402]
R372  1.2K  [SM-7351-CAP-0805]
R373  1.2K  [SM-7351-CAP-0805]
R374  1.2K  [SM-7351-CAP-0805]
R375  1.2K  [SM-7351-CAP-0805]
R376  1.2K  [SM-7351-CAP-0805]
R377  0  [SM-7351-RES-0402]
R378  1.2K  [SM-7351-CAP-0805]
R379  49.9  [SM-7351-CAP-0805]
R380  0  [SM-7351-RES-0402]
R381  0  [SM-7351-RES-0402]
R382  25K  [SM-7351-RES-0603]
R383  2.2K  [sm-7351-res-0402]
R384  2.2K  [sm-7351-res-0402]
R385  0  [SM-7351-RES-0402]
R386  150  [SM-7351-RES-0402]
R387  0  [SM-7351-RES-0402]
R388  150  [SM-7351-RES-0402]
R389  150  [SM-7351-RES-0402]
R390  150  [SM-7351-RES-0402]
R391  150  [SM-7351-RES-0402]
R392  150  [SM-7351-RES-0402]
R393  0  [SM-7351-RES-0402]
R394  0  [SM-7351-RES-0402]
R395  150  [SM-7351-RES-0402]
R396  150  [SM-7351-RES-0402]
R800  10K  [SM-7351-RES-0402]
U28  SN74LVC1G07  [u_5_dck]
U72  SN65HVS882  [u_28_pwp]
U73  TPIC2810  [u_16_d]
sheet Pg29: Profibus
U1  AM5749ABZXEA  [BGA23X23-760-117M]  (sections -1,-10,-11,-12,-13,-14,-15,-16,-17,-18,-19,-2,-20,-21,-22,-23,-24,-25,-26,-27,-28,-29,-3,-4,-5,-6,-7,-8,-9)

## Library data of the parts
C6 C13 C22 C110 C125 C317 C458 = 1C_10uFCapacitor16V10%0805
C7-C12 C14-C17 C28 C105 C112-C115 C118 C120 C127 C195 C207 C210 C400 C401 C403-C406 C451 C453 C548 C550-C553 = 1C_0.01uFCapacitor16V10%0402
C209 C286-C300 = GRT155R61E105KE01D: DescriptiveText: CAP, CER, 1 UF, 10%, 25V, X5R, 0402; Mfr: MURATA
C24 C411 C412 C440 C441 = 1C_100uFCapacitor16V20%ElecPoly
C20 C21 C102-C104 C107-C109 C111 C116 C117 C119 C122-C124 C126 C415 C417 C454-C457 C460 C549 = C0402C104J4RACTU: DescriptiveText: CAP, CER, 0.1 uF, 16V, 5%, X7R, 0402; Mfr: KEMET
J40-J43 J47 = 2H_Header_0
J46 = 2H_Header_4x1
R14 R15 R19 R20 R23-R31 R77-R96 R98 R105 R106 R112 R121-R130 R132-R137 R139 R140 R142 R148 R150 R151 R154 R367 R369 R371 R377 R380 R381 R385 R387 R393 R394 R428 R572 R588 R638 R657 R658 R678 R679 R794 R797 R854 R930-R934 = 1R_ZeroOhmResistor1_16W0402
R639 R640 R801 = LVK12R050DER
R641 = LVK12R010DER
R642 = LVK12R020FER: DescriptiveText: Resistor 0.02ohm 0.5W Sense 1% 1206
R18 R22 R107 R153 R366 R425 R430-R432 R570 R571 R798-R800 R810 R811 R814 R895 R896 R899 R900 = RMCF0402FT10K0: DescriptiveText: RES, THICK FILM,10K OHM, 1%, 0.063W, SMT0402; Mfr: STACKPOLE ELECTRONICS
SCKT1 = AM57XX_SOCKET: DNI: DNI
C23 C459 = 1C_1uFCapacitor50V10%0603
C25 C26 = C0402C270J5GACTU: DescriptiveText: CAP, CER, 27 PF, 50V, 5%, NP0, 0402; Mfr: KEMET
C27 = C1005X7R1H104K050BE: DescriptiveText: CAP, CER, 0.1UF, 50V, 10%, X7R, 0402; Mfr: TDK CORPORATION
C301 C302 C318 C382 C383 C392 C399 C402 C562 = 1C_2.2uFCapacitor6.3V20%X5R0402
C450 C452 = 1C_10uFCapacitor6.3V20%0603
C205 C208 C464-C468 C471 C472 C578 = 1C_2.2uF16V10%SMD0805
D1 = 1E_Diode_15ARect_rev45V: TIIntPartnumber: _1E0014
D2 = SMCJ5.0A: DescriptiveText: DIODE, TVS DIODE, 5VWM, 9.2VC, SMC; Mfr: LITTEL FUSE
D24 D25 = TLVH431_0: DescriptiveText: Adjustable Precision Shunt Regulator; Mfr: TI; MfrNum: TLVH431CDBZT; PartName: Adjustable Precision Shunt Regulator
F1 = 1P_Fuse_0
J1 = 2J_Conn_PwrJack_RAPC712
J2 = 2C_Conn_LeadScrewDown_2pin
Q26 Q27 = 1Q_MOSFET_PChan_FDT434P_0: DescriptiveText: TRANS GP PNP 60V .6A; Mfr: ON Semi; MfrNum: MMBT2907AWT1G; PartName: TRANS GP PNP 60V .6A
R16 R17 R21 = 1R_1KOhmResistor1_16W0402
R894 R898 = RMCF0402FT499R: DescriptiveText: RES, THICK FILM, 499 OHM, 0.063W, 1%, 0402, SMD; Mfr: STACKPOLE ELECTRONICS
R897 R901 = RMCF0402FT24K3: DescriptiveText: RES, THICK FILM, 24.3K OHM, 1%, 0.063W, SMT0402; Mfr: STACKPOLE ELECTRONICS
SW3 = 2W_Switch_Pushbuttonsmd
TP1 TP8-TP11 = 2H_TestPointThroughHole
TP2 TP3 TP6 TP7 TP21 = 2H_Testpoint_SMD1mmCircle
U50 = TPD1E10B06DPYR
U28 U96 = SN74LVC1G07DCKRE4
Y2 = 1Y_Crystal16.384MHz
C268-C271 C276-C280 = 1C_47uFCapacitor10V20%SMD1206
C272-C275 C281-C285 C416 = 1C_4.7uFCapacitor16V10%0603
C418 C419 = 1C_22uFCapacitor16V10%0805
C461 C462 = 1C_10uFCapacitor35V10%0805
C463 = 1C_1.1nFCapacitor50V5%0603
C476 = 1C_2.2uFCapacitor10V20%smd0402
D20 = PMEG2010BELD,315
L12-L20 = SRP4012TA-1R0M: DescriptiveText: INDUCTOR, POWER, 1.0UH, 4.2A, 20%, SMD; Mfr: BOURNS INC
L22 = 1L_0.1Asmd
L28 = 1L_0.5Asmd
R419 = 1R_100KOhmResistor1_16W0402
R424 = 1R_1.62MOhmResistor1_16W0402
R427 = 1R_180KOhmResistor1_16W0402
R646 = 1R_51Kohm1_16W1%smd0402
R647 = 1R_158Kohm1_16W1%smd0402
R648 = 1R_18.2Kohm1_16W1%smd0402
R97 R138 R141 R656 R742 = 1R_ZeroOhmResistor1_16W0603
R680 = 1R_10KOhmResistor1_10W1%0402
R681 = 1R_19.6KohmResistor1_16W1%0402
U3 = TPS6590379ZWSR
U62 = TPS63010YFFR
U79 = TPS61085DGKT
U86 = LP38693MP-ADJ_NOPB
U4 = 1A_S25FL256S_QSPI
C106 C121 = 1C_4700pFCapacitor50V10%0402
J3 J5 = 2J_ConnectorRJ45_10_100MbAMDIX
R76 R104 R108-R111 R120 R131 R152 R155-R158 R383 R384 = 1R_2.2KOhmResistor1_16W0402
R99-R102 R143-R146 = 1R_49.9OhmResistor1_16W0402
R103 R147 = 1R_4.87Kohm1_16W1%smd0402
U9 U13 = TLK105LRHBR
U68 U69 = SN74LVC1G08DCKR
C196 = 1C_0.001uFCapacitor50V5%0402
C197-C204 = C1005X7R1H223K050BE: DescriptiveText: CAP, CER, 22 nF, 10%, 50V,  X7R, 0402, SMD; Mfr: TDK CORPORATION
C206 = C3216X5R1H106K160AB: DescriptiveText: CAP, CER, 10 UF, 10%, 50V,  X5R, 1206, SMD; Mfr: TDK
D5-D12 = 5988170107F
J37 = 2H_Header15x2_0.1in_Female
R368 R370 R372-R376 R378 = ERJ-6ENF1201V: DescriptiveText: RES, THICK FILM, 1.2K OHM, 1%, 0.125W, SMT0805; Mfr: PANASONIC
R379 = ERJ-6ENF49R9V: DescriptiveText: RES, THICK FILM, 49.9 OHM, 1%, 0.125W, 0805; Mfr: PANASONIC
R382 = 1R_25Kohm1_10W0.1%smd0603
R386 R388-R392 R395 R396 = 1R_150ohm1_16W1%SMD0402
U72 = 1A_SN65HVS882
U73 = 1A_TPIC2810: MfrNum: TPIC2810D
U1 = AM5749ABZXEA: DescriptiveText: Dual Cortex A15 Dual C66X SOC AM574x

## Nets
AGNDFRAME_PRU1ETH0: C106.2 J3.SHLD1 J3.SHLD2
AGNDFRAME_PRU1ETH1: C121.2 J5.SHLD1 J5.SHLD2
DGND: C6.2 C7.2 C8.2 C9.2 C10.2 C11.2 C12.2 C13.2 C14.2 C15.2 C16.2 C17.2 C20.2 C21.2 C22.2 C23.2 C24.2(NEG) C25.1 C26.1 C27.1 C28.2 C102.2 C103.2 C104.2 C105.2 C106.1 C107.2 C108.2 C109.2 C110.2 C111.2 C112.2 C113.2 C114.2 C115.2 C116.2 C117.2 C118.2 C119.2 C120.2 C121.1 C122.2 C123.2 C124.2 C125.2 C126.2 C127.2 C195.2 C196.2 C197.2 C198.2 C199.2 C200.2 C201.2 C202.2 C203.2 C204.2 C205.2 C206.2 C207.2 C208.2 C209.2 C210.2 C268.2 C269.2 C270.2 C271.2 C272.2 C273.2 C274.2 C275.2 C276.2 C277.2 C278.2 C279.2 C280.2 C281.2 C282.2 C283.2 C284.2 C285.2 C286.2 C287.2 C288.2 C289.2 C290.2 C291.2 C292.2 C293.2 C294.2 C295.2 C296.2 C297.2 C298.2 C299.2 C300.2 C301.2 C302.2 C317.2 C318.2 C382.2 C383.2 C392.2 C399.2 C400.2 C401.2 C402.2 C403.2 C404.2 C405.2 C406.2 C411.2(NEG) C412.2(NEG) C415.2 C416.2 C417.2 C418.2 C419.2 C440.2(NEG) C441.2(NEG) C450.2 C451.2 C452.2 C453.2 C458.2 C459.2 C460.2 C461.2 C462.2 C463.2 C464.2 C465.2 C466.1 C467.1 C468.2 C471.2 C472.2 C476.2 C548.2 C550.2 C551.2 C552.2 C553.2 C562.2 C578.2 D2.2 J1.2 J1.3 J2.2 J3.8 J5.8 J37.17 J37.29 J37.30 J46.1 R16.2(P2) R103.1(P1) R104.1(P1) R108.1(P1) R109.1(P1) R110.1(P1) R111.1(P1) R147.1(P1) R155.1(P1) R156.1(P1) R157.1(P1) R158.1(P1) R380.1(P1) R381.1(P1) R382.1(P1) R425.2 R427.1(P1) R430.2 R431.2 R432.2 R570.2 R571.2 R648.1(P1) R680.1 R798.1 R810.2 R934.2(P2) SCKT1.MCH2 SCKT1.MCH4 SW3.1 SW3.2 TP8.1 TP9.1 TP10.1 TP11.1 U1.A1(VSS) U1.A2(VSS) U1.A6(VSS) U1.A14(VSS) U1.A23(VSS) U1.A28(VSS) U1.AA8(VSS) U1.AA9(VSS) U1.AA10(VSS) U1.AA11(VSSA_USB) U1.AA14(VSS) U1.AA15(VSS) U1.AA20(VSS) U1.AB11(VSSA_USB) U1.AB14(VSS) U1.AB20(VSS) U1.AD1(VSS) U1.AD10(VSSA_USB3) U1.AD13(VSSA_PCIE) U1.AD19(VSSA_HDMI) U1.AD24(VSS) U1.AE10(VSSA_SATA) U1.AE13(VSSA_PCIE) U1.AE19(VSSA_HDMI) U1.AG1(VSS) U1.AH1(VSS) U1.AH2(VSS) U1.AH8(VSS) U1.AH20(VSS) U1.AH28(VSS) U1.B1(VSS) U1.D13(VSS) U1.D19(VSS) U1.E13(VSS) U1.E19(VSS) U1.F1(VSS) U1.F7(VSS) U1.G7(VSS) U1.G8(VSS) U1.G9(VSS) U1.H12(VSS) U1.J12(VSS) U1.J15(VSS) U1.J28(VSS) U1.K1(VSS) U1.K4(VSS) U1.K5(VSS) U1.K15(VSS) U1.K24(VSS) U1.K25(VSS) U1.L13(VSS) U1.L14(VSS) U1.M19(VSS) U1.N14(VSS) U1.N15(VSS) U1.N19(VSS) U1.N24(VSS) U1.N25(VSS) U1.P28(VSS) U1.R1(VSS) U1.R12(VSS) U1.R13(VSS) U1.R15(VSS) U1.R21(VSS) U1.T10(VSS) U1.T11(VSS) U1.T12(VSS) U1.T14(VSS) U1.T15(VSS) U1.T17(VSS) U1.T18(VSS) U1.T21(VSS) U1.U14(VSSA_VIDEO) U1.U15(VSS) U1.U17(VSS) U1.U20(VSS) U1.U21(VSS) U1.V15(VSS) U1.V17(VSS) U1.W1(VSS) U1.W15(VSS) U1.W24(VSS) U1.W25(VSS) U1.W28(VSS) U3.A1(PKG_GND) U3.A4(REFGND1) U3.A7(GNDANA) U3.A13(PKG_GND) U3.B2(GPADC_IN0) U3.B8(SYNCDCDC) U3.B10(PKG_GND) U3.B11(PKG_GND) U3.C2(GPADC_IN1) U3.C3(GPADC_IN2) U3.C12(SMPS12_FBK_GND) U3.D4(SMPS7_GND) U3.D5(SMPS7_GND) U3.D6(PKG_GND) U3.D7(PKG_GND) U3.D10(SMPS1_GND) U3.E4(SMPS7_GND) U3.E7(GNDANA) U3.E8(PKG_GND) U3.E9(SMPS1_GND) U3.E10(SMPS1_GND) U3.F4(SMPS4_GND) U3.F5(GNDANA) U3.F6(PKG_GND) U3.F7(PKG_GND) U3.F9(SMPS2_GND) U3.F10(SMPS2_GND) U3.G4(SMPS4_GND) U3.G5(SMPS4_GND) U3.G7(PKG_GND) U3.G10(SMPS2_GND) U3.H4(SMPS5_GND) U3.H5(SMPS5_GND) U3.H6(PKG_GND) U3.H7(PKG_GND) U3.H10(SMPS3_GND) U3.J4(SMPS5_GND) U3.J6(PKG_GND) U3.J9(SMPS3_GND) U3.J10(SMPS3_GND) U3.K3(SMPS45_FDBK_GND) U3.L5(SMPS6_GND) U3.L6(SMPS6_GND) U3.L7(SMPS9_GND) U3.L8(SMPS9_GND) U3.L9(SMPS8_GND) U3.L10(SMPS8_GND) U3.M1(PKG_GND) U3.M2(PKG_GND) U3.M12(GNDDIG) U3.M13(GNDANA) U3.N1(PKG_GND) U3.N2(VIO_GND) U3.N13(PKG_GND) U4.10(VSS) U9.TPAD U13.TPAD U28.3(GND) U50.2 U62.B4(SYNC) U62.C1(PGND) U62.C2(PGND) U62.C3(GND) U62.D3(GND) U62.E4(GND) U68.3(GND) U69.3(GND) U72.28(GND) U72.TH_PD(THRM) U73.7(A2) U73.8(~{G}) U73.9(A0) U73.10(A1) U73.16(GND) U79.4(GND) U86.5(GND) U96.3(GND) ; also on sheet 1 2 3 4 5 6 8 9 10 11 12 14 15 16 17 18 26 27 28 29 30 31 32 33 34
V1_8D: C405.1 C406.1 D24.3(Anode) D25.3(Anode) Q26.3(COLLECTOR) Q27.3(COLLECTOR) R658.1(P1) R897.1 R901.1 R933.1(P1) U1.AA7(VDDS_MLBP) U1.AA18(VDDS18V_DDR1) U1.AA19(VDDS18V_DDR1) U1.G18(VDDS18V) U1.H17(VDDS18V) U1.J21(VDDS18V_DDR2) U1.J22(VDDS18V_DDR2) U1.M8(VDDS18V) U1.M9(VDDS18V) U1.N8(VDDS18V) U1.N21(VDDS18V_DDR2) U1.P8(VDDS18V) U1.P20(VDDS18V_DDR2) U1.P21(VDDS18V_DDR2) U1.R8(VDDS18V) U1.T8(VDDS18V) U1.V21(VDDS18V) U1.V22(VDDS18V) U1.W17(VDDS18V) U1.W18(VDDS18V) U1.W21(VDDS18V_DDR1) U1.Y7(VDDS_MLBP) U1.Y21(VDDS18V_DDR1) ; also on sheet 5 26 28 30 33
V1_8PHY_HDMI: U1.Y17(VDDA_HDMI) ; also on sheet 33
V1_8PHY_LDO3: C392.1 U3.K11(LDO3_OUT) ; also on sheet 33
V1_8PHY_LDO4: R854.1(P1) ; also on sheet 33
V1_8PHY_PCIE: U1.AA16(VDDA_PCIE1) U1.AA17(VDDA_PCIE0) U1.W14(VDDA_PCIE) ; also on sheet 33
V1_8PHY_SATA: U1.V13(VDDA_SATA) ; also on sheet 33
V1_8PHY_USB: U1.AA13(VDDA_USB1) U1.AB12(VDDA_USB2) U1.W12(VDDA_USB3) ; also on sheet 33
V1_8PLL: C382.1 U1.AD16(VDDA_OSC) U1.AE16(VDDA_OSC) U3.B5(LDOLN_OUT) ; also on sheet 33
V1_8PLLA: U1.M14(VDDA_ABE_PER) U1.N16(VDDA_MPU) U1.R14(VDDA_GPU) U1.R17(VDDA_IVA) ; also on sheet 33
V1_8PLLB: U1.N11(VDDA_DEBUG) U1.N12(VDDA_DSP_EVE) U1.P14(VDDA_VIDEO) U1.P15(VDDA_GMAC_CORE) U1.P16(VDDA_DDR) ; also on sheet 33
V3_3D: C28.1 C104.1 C105.1 C107.1 C113.1 C119.1 C120.1 C122.1 C127.1 C209.1 C210.1 C450.1 C451.1 J46.3 Q26.2(EMMITTER) R18.2 R22.2 R76.2(P2) R77.2(P2) R78.2(P2) R89.2(P2) R97.1(P1) R99.1(P1) R100.1(P1) R101.1(P1) R102.1(P1) R107.2 R120.2(P2) R121.2(P2) R122.2(P2) R131.2(P2) R134.2(P2) R141.1(P1) R143.1(P1) R144.1(P1) R145.1(P1) R146.1(P1) R152.2(P2) R153.2 R366.2 R383.2(P2) R384.2(P2) R419.2(P2) R678.2(P2) R679.2(P2) R742.1(P1) R799.2 R800.2 R811.1 R814.1 R894.2 R896.2 U1.AB6(VDDSHV7) U1.AB7(VDDSHV7) U1.AD5(VDDSHV6) U1.AD7(VDDSHV6) U1.AE7(VDDSHV6) U1.AF5(VDDSHV6) U1.B6(VDDSHV2) U1.B23(VDDSHV3) U1.C24(VDDSHV4) U1.D10(VDDSHV2) U1.D16(VDDSHV3) U1.D22(VDDSHV3) U1.E3(VDDSHV1) U1.E5(VDDSHV1) U1.E10(VDDSHV2) U1.E16(VDDSHV3) U1.E22(VDDSHV3) U1.G4(VDDSHV1) U1.G5(VDDSHV1) U1.G15(VDDSHV3) U1.H8(VDDSHV1) U1.H9(VDDSHV1) U1.H10(VDDSHV2) U1.H11(VDDSHV2) U1.H15(VDDSHV3) U1.H16(VDDSHV3) U1.H18(VDDSHV3) U1.H19(VDDSHV3) U1.J8(VDDSHV11) U1.K8(VDDSHV11) U1.N4(VDDSHV10) U1.N5(VDDSHV10) U1.P10(VDDSHV10) U1.R7(VDDSHV10) U1.R10(VDDSHV10) U1.T4(VDDSHV10) U1.T5(VDDSHV10) U1.U10(VDDSHV9) U1.V12(VDDSHV5) U1.W4(VDDSHV9) U1.W5(VDDSHV9) U3.D9(VIO_IN) U3.J8(SMPS9_FBK) U4.2(VCC) U4.14(VIO/RFU) U9.21(VDD33_IO) U13.21(VDD33_IO) U68.5(VCC) U69.5(VCC) U73.1(VCC) ; also on sheet 2 3 4 5 6 8 9 10 11 12 14 15 17 18 26 27 28 29 30 31 32 33 34
V3_3D_PRU1ETH0JCK: C102.1 C103.1 J3.3 J3.4 R77.1(P1)
V3_3D_PRU1ETH1JCK: C116.1 C117.1 J5.3 J5.4 R121.1(P1)
V3_3USB: C399.1 C400.1 C401.1 U1.AA12(VDDA33V_USB1) U1.Y12(VDDA33V_USB2) U3.B9(LDOUSB_OUT)
V3_7LCD: C472.1 R681.1 U86.3(VOUT) ; also on sheet 5
V5_0D: C208.1 C418.1 C419.1 C476.1 J37.27 J37.28 R386.1(P1) R388.1(P1) R389.1(P1) R390.1(P1) R391.1(P1) R392.1(P1) R395.1(P1) R396.1(P1) R424.2(P2) U62.E1(VOUT) U62.E2(VOUT) ; also on sheet 4 14 15 31
V5_0D_EN: R419.1(P1) U62.A4(EN)
V5_0DFB: R424.1(P1) R427.2(P2) U62.E3(FB)
V5_0VOP: C195.1 C205.1 C207.1 U28.5(VCC) U72.15(5VOP)
V12_0D: C196.1 C461.1 C462.1 D20.1(CATHODE) J37.2 J37.4 J37.6 J37.8 J37.10 J37.12 J37.14 J37.16 R379.1 R647.2(P2) ; also on sheet 18
VDD_CORE: R640.2(I2) R931.1(P1) U1.H13(VDD) U1.H14(VDD) U1.J17(VDD) U1.J18(VDD) U1.L7(VDD) U1.L8(VDD) U1.N10(VDD) U1.N13(VDD) U1.P11(VDD) U1.P12(VDD) U1.P13(VDD) U1.R11(VDD) U1.R16(VDD) U1.R19(VDD) U1.T13(VDD) U1.T16(VDD) U1.T19(VDD) U1.U8(VDD) U1.U9(VDD) U1.U13(VDD) U1.U16(VDD) U1.V8(VDD) U1.V16(VDD) U3.B1(SMPS7_FDBK) ; also on sheet 33
VDD_DSPEVE: R642.2(I2) U1.J13(VDD_DSPEVE) U1.K10(VDD_DSPEVE) U1.K11(VDD_DSPEVE) U1.K12(VDD_DSPEVE) U1.K13(VDD_DSPEVE) U1.L10(VDD_DSPEVE) U1.L11(VDD_DSPEVE) U1.L12(VDD_DSPEVE) U1.M10(VDD_DSPEVE) U1.M11(VDD_DSPEVE) U1.M12(VDD_DSPEVE) U1.M13(VDD_DSPEVE) U3.K2(SMPS45_FDBK) ; also on sheet 33
VDD_GPU: C268.1 L17.2 U1.U11(VDD_GPU) U1.U12(VDD_GPU) U1.V10(VDD_GPU) U1.V11(VDD_GPU) U1.V14(VDD_GPU) U1.W10(VDD_GPU) U1.W11(VDD_GPU) U1.W13(VDD_GPU) U3.K6(SMPS6_FBK) ; also on sheet 33
VDD_IVA: C270.1 L19.2 U1.U18(VDD_IVA) U1.U19(VDD_IVA) U1.V18(VDD_IVA) U1.V19(VDD_IVA) U3.L11(SMPS8_FDBK) ; also on sheet 33
VDD_MPU: R641.2(I2) U1.K17(VDD_MPU) U1.K18(VDD_MPU) U1.L15(VDD_MPU) U1.L16(VDD_MPU) U1.L17(VDD_MPU) U1.L18(VDD_MPU) U1.L19(VDD_MPU) U1.M15(VDD_MPU) U1.M16(VDD_MPU) U1.M17(VDD_MPU) U1.M18(VDD_MPU) U1.N17(VDD_MPU) U1.N18(VDD_MPU) U1.P17(VDD_MPU) U1.P18(VDD_MPU) U1.R18(VDD_MPU) U3.B13(SMPS12_FBK) ; also on sheet 33
VDD_RTC: C402.1 R930.1(P1) U3.A5(LDO9_OUT)
VDDS_DDR: R639.1(I1) R656.1(P1) R801.1(I1) U3.K13(SMPS3_FDBK) ; also on sheet 1 9 16
AM57XX_GPIO_IND_LDn: R371.2(P2) R800.1 U1.AF4(VIN1A_D15/GPIO)
AM57XX_I2C1_SCL: R384.1(P1) R385.2(P2) R393.2(P2) U1.C20(I2C1_SCL)
AM57XX_I2C1_SDA: R383.1(P1) R387.2(P2) R394.2(P2) U1.C21(I2C1_SDA)
AM57XX_PRU1ETH0_MRCLK: R83.2(P2) U1.Y1(UART3_TXD/PR1_MII0_MR0CLK)
AM57XX_PRU1ETH0_RXDV: R86.2(P2) U1.V2(UART3_RXD/PR1_MII0_RXDV)
AM57XX_PRU1ETH1_MRCLK: R129.2(P2) ; also on sheet 28
AM57XX_PRU1ETH1_TXCLK: R123.2(P2) U1.C1(VIN2A_D6/PR1_MII_MT1_CLK) ; also on sheet 31
AM57XX_PRU1ETH1_TXD0: R125.2(P2) ; also on sheet 28
AM57XX_PRU1ETH1_TXD1: R126.2(P2) ; also on sheet 28
AM57XX_PRU1ETH1_TXD2: R127.2(P2) U1.E6(VIN2A_D9/PR1_MII1_TXD2)
AM57XX_PRU1ETH1_TXD3: R128.2(P2) U1.F5(VIN2A_D8/PR1_MII1_TXD3) ; also on sheet 31
AM57XX_PRU1ETH1_TXEN: R124.2(P2) U1.E4(VIN2A_D7/PR1_MII1_TXEN)
AM57XX_PRU1ETH_MDCLK: R96.2(P2) R140.2(P2) U1.D3(VIN2A_D10/PR1_MDIO_MDCLK) ; also on sheet 31
AM57XX_PRU1ETH_MDDATA: R98.2(P2) R142.2(P2) U1.F6(VIN2A_D11/PR1_MDIO_DATA)
AM57XX_RGMII0_RD0: R81.2(P2) ; also on sheet 26
AM57XX_RGMII0_RD1: R84.2(P2) ; also on sheet 26
AM57XX_RGMII0_RD2: R80.2(P2) ; also on sheet 26
AM57XX_RGMII0_RD3: R85.2(P2) ; also on sheet 26
AM57XX_RGMII0_RXCLK: R79.2(P2) ; also on sheet 26
AM57XX_RGMII0_RXCTL: R82.2(P2) ; also on sheet 26
AM57XX_RGMII0_TD0: R88.2(P2) ; also on sheet 26
AM57XX_RGMII0_TD1: R90.2(P2) ; also on sheet 26
AM57XX_RGMII0_TD2: R87.2(P2) ; also on sheet 26
AM57XX_RGMII0_TD3: R94.2(P2) ; also on sheet 26
AM57XX_RGMII0_TXCLK: R92.2(P2) ; also on sheet 26
AM57XX_RGMII0_TXCTL: R91.2(P2) ; also on sheet 26
AM57XX_RGMII1_RD0: R139.2(P2) ; also on sheet 28
AM57XX_RGMII1_RD1: R148.2(P2) ; also on sheet 28
AM57XX_RGMII1_RD2: R150.2(P2) ; also on sheet 28
AM57XX_RGMII1_RD3: R132.2(P2) ; also on sheet 28
AM57XX_RGMII1_RXCLK: R135.2(P2) ; also on sheet 28
AM57XX_RGMII1_RXCTL: R133.2(P2) ; also on sheet 28
AM57XX_RGMII1_TD0: R136.2(P2) ; also on sheet 28
AM57XX_RGMII1_TD1: R137.2(P2) ; also on sheet 28
AM57XX_RGMII1_TD2: R130.2(P2) ; also on sheet 28
AM57XX_SPI1_CS0: R369.2(P2) U1.D17(MCASP4_AXR1/SPI3_CS0)
AM57XX_SPI1_D1: R377.2(P2) U1.A21(MCASP4_FSX/SPI3_D1)
AM57XX_SPI1_SCLK: R367.2(P2) U1.C18(MCASP4_ACLKX/SPI3_SCLK)
AM572X_QSPI_CLK: R24.2(P2) U1.R2(GPMC_A18/QSPI1_SCLK)
AM572X_QSPI_CSn: R30.2(P2) U1.P2(GPMC_CS2/QSPI1_CS0)
AM572X_QSPI_D0: R25.2(P2) U1.U1(GPMC_A16/QSPI1_D0)
AM572X_QSPI_D1: R26.2(P2) U1.P3(GPMC_A17/QSPI1_D1)
AM572X_QSPI_D2: R27.2(P2) U1.U2(GPMC_A15/QSPI_D2)
AM572X_QSPI_D3: R28.2(P2) U1.T2(GPMC_A14/QSPI_D3)
AM572X_QSPI_RTCLK: R23.2(P2) U1.R3(GPMC_A13/QSPI_RTCLK)
DRAIN0: D5.1(Cathode) J37.19 U73.3(DRAIN0)
DRAIN1: D6.1(Cathode) J37.20 U73.4(DRAIN1)
DRAIN2: D7.1(Cathode) J37.21 U73.5(DRAIN2)
DRAIN3: D8.1(Cathode) J37.22 U73.6(DRAIN3)
DRAIN4: D9.1(Cathode) J37.23 U73.11(DRAIN4)
DRAIN5: D10.1(Cathode) J37.24 U73.12(DRAIN5)
DRAIN6: D11.1(Cathode) J37.25 U73.13(DRAIN6)
DRAIN7: D12.1(Cathode) J37.26 U73.14(DRAIN7)
ETH_MDIO_CLK: R95.2(P2) ; also on sheet 26 28
ETH_MDIO_DATA: R105.2(P2) ; also on sheet 26 28
GPIO_PRU1_ETH0_RESETn: R112.2(P2) ; also on sheet 31
GPIO_PRU1_ETH1_RESETn: R154.2(P2) ; also on sheet 31
GPIO_USB2_VBUS_DET: R811.2 U96.4(Y) ; also on sheet 31
GPIO_VPP_PWR_EN: R638.2(P2) ; also on sheet 31
IND_I2C_SCL: R14.2(P2) R393.1(P1) ; also on sheet 5 10 11 18 26 31
IND_I2C_SDA: R15.2(P2) R394.1(P1) ; also on sheet 5 10 11 18 26 31
INDUS_INPUT0: J37.1 R368.2
INDUS_INPUT1: J37.3 R370.2
INDUS_INPUT2: J37.5 R372.2
INDUS_INPUT3: J37.7 R374.2
INDUS_INPUT4: J37.9 R373.2
INDUS_INPUT5: J37.11 R375.2
INDUS_INPUT6: J37.13 R376.2
INDUS_INPUT7: J37.15 R378.2
INDUS_INPUTCLK: R367.1(P1) U72.25(CLK)
INDUS_INPUTCSn: R369.1(P1) U72.24(~{CE})
INDUS_INPUTLDn: R371.1(P1) U72.26(~{LD})
INDUS_INPUTSO: U28.2(A) U72.23(SOP)
PHY_RESETn: U68.2(B) U69.2(B) ; also on sheet 17 26 27 28 32
PMIC_EN: U3.E5(nSLEEP) ; also on sheet 30
PMIC_INT: U3.K1(INT) ; also on sheet 31
PMIC_RESET_IN: R794.1(P1) U3.K9(RESET_IN)
PMIC_RESET_OUTn: R814.2 U3.G6(RESET_OUT) ; also on sheet 32
PRU1ETH0_25MHzCLK: U9.23(XI) ; also on sheet 26
PRU1ETH0_COL: R95.1(P1) R104.2(P2) R105.1(P1) R106.2(P2) U9.29(COL)
PRU1ETH0_CRS: R94.1(P1) U9.27(CRS)
PRU1ETH0_INTn: U9.8(PWRDNn/INTn) ; also on sheet 31
PRU1ETH0_LINKLED: R76.1(P1) R93.2(P2) U9.17(LED_LINK)
PRU1ETH0_MDC: R96.1(P1) U9.20(MDC)
PRU1ETH0_MDIO: R98.1(P1) U9.19(MDIO)
PRU1ETH0_RESETn: U9.18(RESET_N) U68.4(Y)
PRU1ETH0_RXCLK: R83.1(P1) U9.25(RX_CLK)
PRU1ETH0_RXD0: R88.1(P1) R111.2(P2) U9.30(RXD_0)
PRU1ETH0_RXD1: R90.1(P1) R110.2(P2) U9.31(RXD_1)
PRU1ETH0_RXD2: R91.1(P1) R109.2(P2) U9.32(RXD_2)
PRU1ETH0_RXD3: R92.1(P1) R108.2(P2) U9.1(RXD_3)
PRU1ETH0_RXDV: R86.1(P1) U9.26(RX_DV)
PRU1ETH0_RXERR: R87.1(P1) U9.28(RX_ERR)
PRU1ETH0_TXCLK: R79.1(P1) U9.2(TX_CLK)
PRU1ETH0_TXD0: R81.1(P1) U9.4(TXD_0)
PRU1ETH0_TXD1: R84.1(P1) U9.5(TXD_1)
PRU1ETH0_TXD2: R85.1(P1) U9.6(TXD_2)
PRU1ETH0_TXD3: R82.1(P1) U9.7(TXD_3)
PRU1ETH0_TXEN: R80.1(P1) U9.3(TX_EN)
PRU1ETH1_25MHzCLK: U13.23(XI) ; also on sheet 26
PRU1ETH1_COL: R148.1(P1) R150.1(P1) R151.2(P2) R152.1(P1) U13.29(COL)
PRU1ETH1_CRS: R139.1(P1) U13.27(CRS)
PRU1ETH1_INTn: U13.8(PWRDNn/INTn) ; also on sheet 31
PRU1ETH1_LINKLED: R131.1(P1) R138.2(P2) U13.17(LED_LINK)
PRU1ETH1_MDC: R140.1(P1) U13.20(MDC)
PRU1ETH1_MDIO: R120.1(P1) R142.1(P1) U13.19(MDIO)
PRU1ETH1_RESETn: U13.18(RESET_N) U69.4(Y)
PRU1ETH1_RXCLK: R129.1(P1) U13.25(RX_CLK) ; also on sheet 31
PRU1ETH1_RXD0: R133.1(P1) R158.2(P2) U13.30(RXD_0)
PRU1ETH1_RXD1: R135.1(P1) R157.2(P2) U13.31(RXD_1) ; also on sheet 31
PRU1ETH1_RXD2: R136.1(P1) R156.2(P2) U13.32(RXD_2)
PRU1ETH1_RXD3: R137.1(P1) R155.2(P2) U13.1(RXD_3) ; also on sheet 31
PRU1ETH1_RXDV: R130.1(P1) U13.26(RX_DV)
PRU1ETH1_RXERR: R132.1(P1) U13.28(RX_ERR) ; also on sheet 31
PRU1ETH1_TXCLK: R123.1(P1) U13.2(TX_CLK)
PRU1ETH1_TXD0: R125.1(P1) U13.4(TXD_0)
PRU1ETH1_TXD1: R126.1(P1) U13.5(TXD_1) ; also on sheet 31
PRU1ETH1_TXD2: R127.1(P1) U13.6(TXD_2)
PRU1ETH1_TXD3: R128.1(P1) U13.7(TXD_3)
PRU1ETH1_TXEN: R124.1(P1) U13.3(TX_EN)
PRU1ETHER0_RDN: J3.2 R99.2(P2) U9.9(RD-)
PRU1ETHER0_RDP: J3.1 R100.2(P2) U9.10(RD+)
PRU1ETHER0_TDN: J3.6 R101.2(P2) U9.11(TD-)
PRU1ETHER0_TDP: J3.5 R102.2(P2) U9.12(TD+)
PRU1ETHER1_RDN: J5.6 R143.2(P2) U13.9(RD-)
PRU1ETHER1_RDP: J5.5 R144.2(P2) U13.10(RD+)
PRU1ETHER1_TDN: J5.2 R145.2(P2) U13.11(TD-)
PRU1ETHER1_TDP: J5.1 R146.2(P2) U13.12(TD+)
QSPI_CLK: R23.1(P1) R24.1(P1) R31.2(P2)
RSTOUTTOPMIC: U3.E6(nRESWARM) ; also on sheet 32
SPIMEM_CLK: R31.1(P1) U4.16(SCK)
SPIMEM_CSn: R30.1(P1) U4.7(~{CS})
SPIMEM_D0: R25.1(P1) U4.15(SI/IO0)
SPIMEM_D1: R26.1(P1) U4.8(SO/IO1)
SPIMEM_D2: R22.1 R27.1(P1) U4.9(~{WP}/IO2)
SPIMEM_D3: R28.1(P1) R799.1 U4.1(~{HOLD}/IO3)
SYS_RESETn: R29.2(P2) ; also on sheet 5 31 32
VADD33_PRU1ETH0: C112.1 R97.2(P2) U9.14(AVDD33)
VADD33_PRU1ETH1: C118.1 R141.2(P2) U13.14(AVDD33)
VAM572X_DDR1: C6.1 C7.1 C8.1 C9.1 C10.1 C11.1 C12.1 C114.1 C115.1 C441.1(POS) R639.2(I2) U1.AA21(VDDS_DDR1) U1.AA22(VDDS_DDR1) U1.AB21(VDDS_DDR1) U1.AB22(VDDS_DDR1) U1.AB24(VDDS_DDR1) U1.AB25(VDDS_DDR1) U1.AC22(VDDS_DDR1) U1.AD26(VDDS_DDR1) U1.AG20(VDDS_DDR1) U1.AG28(VDDS_DDR1) U1.AH27(VDDS_DDR1) U1.W16(VDDS_DDR1) U1.W27(VDDS_DDR1)
VAM572X_DDR2: C13.1 C14.1 C15.1 C16.1 C17.1 C440.1(POS) C550.1 C551.1 C552.1 C553.1 R801.2(I2) U1.E24(VDDS_DDR2) U1.G22(VDDS_DDR2) U1.G23(VDDS_DDR2) U1.H20(VDDS_DDR2) U1.H21(VDDS_DDR2) U1.H22(VDDS_DDR2) U1.J27(VDDS_DDR2) U1.L20(VDDS_DDR2) U1.L21(VDDS_DDR2) U1.M20(VDDS_DDR2) U1.M21(VDDS_DDR2) U1.T24(VDDS_DDR2) U1.T25(VDDS_DDR2)
VANA_OUT: C302.1 U3.C8(LDOVANA_OUT)
VLDO1_OUT: C383.1 R657.2(P2) U3.C6(LDO1_OUT)
VLDO2_OUT: C318.1 R658.2(P2) U3.B6(LDO2_OUT)
VMAIN: C20.1 C21.1 C22.1 C23.1 C24.1(POS) C272.1 C273.1 C274.1 C275.1 C281.1 C282.1 C283.1 C284.1 C285.1 C317.1 C411.1(POS) C412.1(POS) C415.1 C416.1 C452.1 C453.1 C458.1 C459.1 C464.1 C465.1 C466.2 C467.2 C468.1 C471.1 D2.1 F1.2 L28.1 R19.2(P2) R20.2(P2) TP1.1 U3.A6(LDO12_IN) U3.A9(LDOUSB_IN2) U3.A10(LDO7_LDOUSB_IN) U3.C4(LDO9_IN) U3.C5(LDOLN_IN) U3.C7(VCC1) U3.D11(SMPS1_IN_1) U3.D12(SMPS1_IN_2) U3.D13(SMPS1_IN_3) U3.E1(SMPS7_IN_B1_1) U3.E2(SMPS7_IN_B1_2) U3.E3(SMPS7_IN_B1_3) U3.F1(SMPS4_IN1) U3.F2(SMPS4_IN2) U3.F3(SMPS4_IN3) U3.G11(SMPS2_IN_1) U3.G12(SMPS2_IN_2) U3.G13(SMPS2_IN_3) U3.H11(SMPS3_IN1) U3.H12(SMPS3_IN2) U3.H13(SMPS3_IN3) U3.J1(SMPS5_IN1) U3.J2(SMPS5_IN2) U3.J3(SMPS5_IN3) U3.L12(LDO34_IN) U3.L13(LDO34_IN1) U3.M4(LDO58_IN) U3.M6(SMPS6_IN) U3.M8(SMPS9_IN) U3.M9(SMPS8_IN) U3.N3(LDO6_IN) U3.N4(LDO58_IN) U3.N6(SMPS6_IN) U3.N8(SMPS9_IN) U3.N9(SMPS8_IN) U62.A1(VIN) U62.A2(VIN) U79.6(IN) U79.7(FREQ) U86.4(VIN) U96.5(VCC) ; also on sheet 5 11 31
VPP_CONN: J46.2 R797.1(P1)
VPWRIN_JCK: D1.2(ANODE) J1.1 J2.1
VPWRIN_PREFUSE: D1.1(CATHODE) F1.1
VRTC_OUT: C301.1 R17.2(P2) R794.2(P2) R932.1(P1) U3.A8(LDOVRTC_OUT) ; also on sheet 30
VSDMMC: Q27.2(EMMITTER) R657.1(P1) R898.2 R900.2 U1.W8(VDDSHV8) U1.Y8(VDDSHV8) ; also on sheet 29 33
VSMPS1_2: C276.1 C277.1 L12.2 L13.2 R641.1(I1)
VSMPS1_SW: L12.1 U3.E11(SMPS1_SW_1) U3.E12(SMPS1_SW_2) U3.E13(SMPS1_SW_3)
VSMPS2_SW: L13.1 U3.F11(SMPS2_SW1) U3.F12(SMPS2_SW2) U3.F13(SMPS2_SW3)
VSMPS3: C278.1 L14.2 R656.2(P2)
VSMPS3_SW: L14.1 U3.J11(SMPS3_SW1) U3.J12(SMPS3_SW2) U3.J13(SMPS3_SW3)
VSMPS4_5: C279.1 C280.1 L15.2 L16.2 R642.1(I1)
VSMPS4_SW: L15.1 U3.G1(SMPS4_SW1) U3.G2(SMPS4_SW2) U3.G3(SMPS4_SW3)
VSMPS5_SW: L16.1 U3.H1(SMPS5_SW1) U3.H2(SMPS5_SW2) U3.H3(SMPS5_SW3)
VSMPS6_SW: L17.1 U3.M5(SMPS6_SW) U3.N5(SMPS6_SW)
VSMPS7: C269.1 L18.2 R640.1(I1)
VSMPS7_SW: L18.1 U3.D1(SMPS7_SW1) U3.D2(SMPS7_SW2) U3.D3(SMPS7_SW3)
VSMPS8_SW: L19.1 U3.M10(SMPS8_SW) U3.N10(SMPS8_SW)
VSMPS9: C271.1 L20.2 R742.2(P2)
VSMPS9_SW: L20.1 U3.M7(SMPS9_SW) U3.N7(SMPS9_SW)
VUSB_VBUS2: R21.2(P2) ; also on sheet 14
N12220066: C108.1 C109.1 C110.1 C111.1 U9.13(PFBIN1) U9.15(PFBOUT) U9.24(PFBIN2)
N12225140: J5.11 R122.1(P1)
N12225158: C123.1 C124.1 C125.1 C126.1 U13.13(PFBIN1) U13.15(PFBOUT) U13.24(PFBIN2)
N12225278: J5.10 R151.1(P1)
N12226470: J5.9 R134.1(P1)
N12226568: R153.1 R154.1(P1) U69.1(A)
N15911835: R147.2(P2) U13.16(RBIAS)
N16251668: R385.1(P1) U73.15(SCL)
N16251678: R387.1(P1) U73.2(SDA)
N16700927: J5.12 R138.1(P1)
N16818596: J3.9 R89.1(P1)
N16818719: R107.1 R112.1(P1) U68.1(A)
N16819128: R103.2(P2) U9.16(RBIAS)
N16839102: C206.1 R379.2 U72.14(VCC)
N16839202: R382.2(P2) U72.13(RLIM)
N16839209: R381.2(P2) U72.2(DB1)
N16839216: R380.2(P2) U72.1(DB0)
N16844891: D6.2(Anode) R388.2(P2)
N16844892: D11.2(Anode) R395.2(P2)
N16844893: D12.2(Anode) R396.2(P2)
N16844894: D9.2(Anode) R391.2(P2)
N16844899: D10.2(Anode) R392.2(P2)
N16844909: D5.2(Anode) R386.2(P2)
N16844924: D8.2(Anode) R390.2(P2)
N16844930: D7.2(Anode) R389.2(P2)
N17007255: R366.1 R377.1(P1) U28.4(Y)
N17074741: J3.10 R106.1(P1)
N17144335: R29.1(P1) U4.3(~{RESET})
N17863265: J3.11 R78.1(P1)
N17863276: J3.12 R93.1(P1)
N18868530: R14.1(P1) R572.2(P2) U3.L1(I2C1_SCL_SCK)
N18868533: R15.1(P1) R588.2(P2) U3.L2(I2C1_SDA_SDI)
N18913166: TP7.1 U3.J5(ENABLE1)
N18913202: R17.1(P1) R934.1(P1) U3.K7(BOOT1)
N18913205: R16.1(P1) U3.L3(BOOT0)
N18913322: R18.1 U3.G9(GPIO_7)
N18913403: C26.2 U3.A3(OSC16MIN) Y2.1
N18913412: C25.2 U3.A2(OSC16MOUT) Y2.3
N18913758: C27.2 U3.B7(VBG)
N18914093: C578.1 U3.C1(OSC16MCAP)
N18914190: TP2.1 U3.M11(CLK32KGO)
N18914214: TP3.1 U3.J7(POWERGOOD)
N18914339: SW3.3 SW3.4 U3.G8(PWRON) U50.1
N18914524: TP6.1 U3.C11(RPWRON)
N18915671: R19.1(P1) U3.B3(VCC_SENSE)
N18915723: R20.1(P1) U3.A11(VCC_SENSE2)
N18915943: R21.1(P1) U3.D8(VBUS)
N19795587: R425.1 U3.B12(GPIO_0)
N19795594: R428.1(P1) U3.C13(GPIO_1)
N19795604: R430.1 U3.A12(GPIO_2)
N19795606: R431.1 U3.H9(GPIO_3)
N19795618: R570.1 U3.C10(GPIO_5)
N19795620: R571.1 U3.N11(GPIO_6)
N19795629: R432.1 U3.K10(GPIO_4)
N19796448: R572.1(P1) U3.M3(I2C2_SCL_SCE)
N19796451: R588.1(P1) U3.H8(I2C2_SDA_SDO)
N19923823: C286.1 U1.J10(CAP_VDDRAM_DSPEVE1)
N19923824: C287.1 U1.J9(CAP_VDDRAM_DSPEVE2)
N19923825: C288.1 U1.J16(CAP_VBBLDO_MPU)
N19923831: C292.1 U1.K19(CAP_VDDRAM_MPU2)
N19923832: C291.1 U1.K16(CAP_VDDRAM_MPU1)
N19923833: C290.1 U1.K9(CAP_VBBLDO_DSPEVE)
N19923834: C289.1 U1.J19(CAP_VDDRAM_CORE2)
N19923844: C293.1 U1.L9(CAP_VDDRAM_CORE1)
N19923845: C294.1 U1.P19(CAP_VDDRAM_CORE4)
N19923846: C295.1 U1.R20(CAP_VBBLDO_IVA)
N19923850: C299.1 U1.Y15(CAP_VDDRAM_CORE3)
N19923851: C298.1 U1.Y14(CAP_VBBLDO_GPU)
N19923852: C297.1 U1.Y13(CAP_VDDRAM_GPU)
N19923853: C296.1 U1.T20(CAP_VDDRAM_IVA)
N19923865: C300.1 U1.Y16(CAP_VDDRAM_CORE5)
N20127658: C403.1 R930.2(P2) R931.2(P2) U1.AB15(VDD_RTC)
N20128389: C404.1 R932.2(P2) R933.2(P2) U1.AB13(VDDA_RTC)
N20190363: C454.2 J40.2 R639.4(SENS2)
N20190375: C454.1 J40.1 R639.3(SENS1)
N20190748: C455.2 J41.1 R640.3(SENS1)
N20190772: C455.1 J41.2 R640.4(SENS2)
N20190931: C456.2 J42.1 R641.3(SENS1)
N20190955: C456.1 J42.2 R641.4(SENS2)
N20191205: C457.2 J43.1 R642.3(SENS1)
N20191229: C457.1 J43.2 R642.4(SENS2)
N20202943: TP21.1 U3.F8(REGEN1)
N20275163: C460.1 U79.8(SS)
N20287248: R647.1(P1) R648.2(P2) U79.2(FB)
N20287275: R646.2(P2) U79.1(COMP)
N20287568: C463.1 R646.1(P1)
N20287584: D20.2(ANODE) L28.2 U79.5(SW)
N20594970: R678.1(P1) U86.1(VEN)
N20595300: R679.1(P1) U79.3(EN)
N20619479: R680.2 R681.2 U86.2(ADJ)
N20664562: L22.1 U62.B1(L1) U62.B2(L1)
N20664572: C417.1 U62.A3(VINA) U62.B3(VINA1) U62.C4(~{PS}) U62.D4(VSEL)
N20665027: L22.2 U62.D1(L2) U62.D2(L2)
N21620210: C197.1 R368.1 U72.3(IP0)
N21620213: C198.1 R370.1 U72.5(IP1)
N21620216: C199.1 R372.1 U72.7(IP2)
N21620219: C200.1 R374.1 U72.9(IP3)
N21620222: C201.1 R373.1 U72.11(IP4)
N21620225: C202.1 R375.1 U72.18(IP5)
N21620228: C203.1 R376.1 U72.20(IP6)
N21620231: C204.1 R378.1 U72.22(IP7)
N21685968: C548.1 R797.2(P2) U1.K14(RSVK14)
N21685998: J46.4 R638.1(P1) R798.2
N21823186: C549.2 J47.2 R801.4(SENS2)
N21823194: C549.1 J47.1 R801.3(SENS1)
N22373612: R428.2(P2) R810.1 U96.2(A)
N22641301: D24.2(Cathode) Q26.1(BASE) R894.1 R895.1
N22641309: D24.1(REF) R895.2 R896.1 R897.2
N22641383: D25.2(Cathode) Q27.1(BASE) R898.1 R899.1
N22641391: D25.1(REF) R899.2 R900.1 R901.2
N22644059: C562.1 R854.2(P2) U3.K12(LDO4_OUT)

Not connected (* = marked no-connect by the designer): J3 7*; J5 7*; J37 18; SCKT1 MCH1* MCH3*; U1 A27(RSVA27)* B28(RSVB28)* Y5(RSVY5)* Y10(RSVY10)*; U3 B4(GPADC_REF)* C9(LDO7_OUT)* K4(LDO5_OUT)* K5(LDO8_OUT)* K8(PWRDOWN)* L4(LDO6_OUT)* N12(VPROG/TESTV)*; U4 4(NC4)* 5(NC5)* 6(NC6)* 11(NC11)* 12(NC12)* 13(NC13)*; U9 22(XO)*; U13 22(XO)*; U28 1(NC)*; U72 4(RE0)* 6(RE1)* 8(RE2)* 10(RE3)* 12(RE4)* 16(TOK)* 17(RE5)* 19(RE6)* 21(RE7)* 27(SIP)*; U96 1(NC)*; Y2 2(NC0)* 4(NC1)*

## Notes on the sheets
sheet 20
- Main 5VDC Power Input
- Sufficient capacitance needed to
  hold up VMAIN (over 2.7V) for at
  least 1ms after power supply
  shut off. AM57xx device will be
  in POR reset. This will allow
  the PMIC to properly execute its
  power-down sequence.
- Clamp circuits added to guarantee the 3.3V
  supplies V3_3D and VSDMMC never become
  more than 2V above V1_8D during start-up
  or shut-down.
- Circuit needed to detect VPWRIN
  collapse which can initiate a PMIC
  power shut-down sequence such as a
  TPS3808.  Please refer to the
  AM571x IDK EVM for an example.  The
  circuit must drive the PMIC
  RESET_IN low to initiate this
  shut-down sequence.
- It has been later determined that the clamp
  circuit on VSDMMC is not sufficient and the
  PMIC was enhanced to better control
  shut-down sequencing.  Therefore, the
  VDSMMC clamp is no longer required. The
  power-down sequence defined in the Data
  Manual must be met.
- Power On
  Switch
sheet 21
- Industrial INPUTS
- Digital OUTPUTS
- I/O Expansion Header
sheet 22
- Note: MDIO Address = 0x00
sheet 24
- Note: MDIO Address = 0x01
